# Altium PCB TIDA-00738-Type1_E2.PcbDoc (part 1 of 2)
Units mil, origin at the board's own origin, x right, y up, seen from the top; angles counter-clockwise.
Board outline 4723.41 x 3650 mil, 4 copper layers (Top Layer, GND, PWR, Bottom Layer), stack 79.834 mil thick; 251 components, 112 nets, 616 pads, 221 vias.
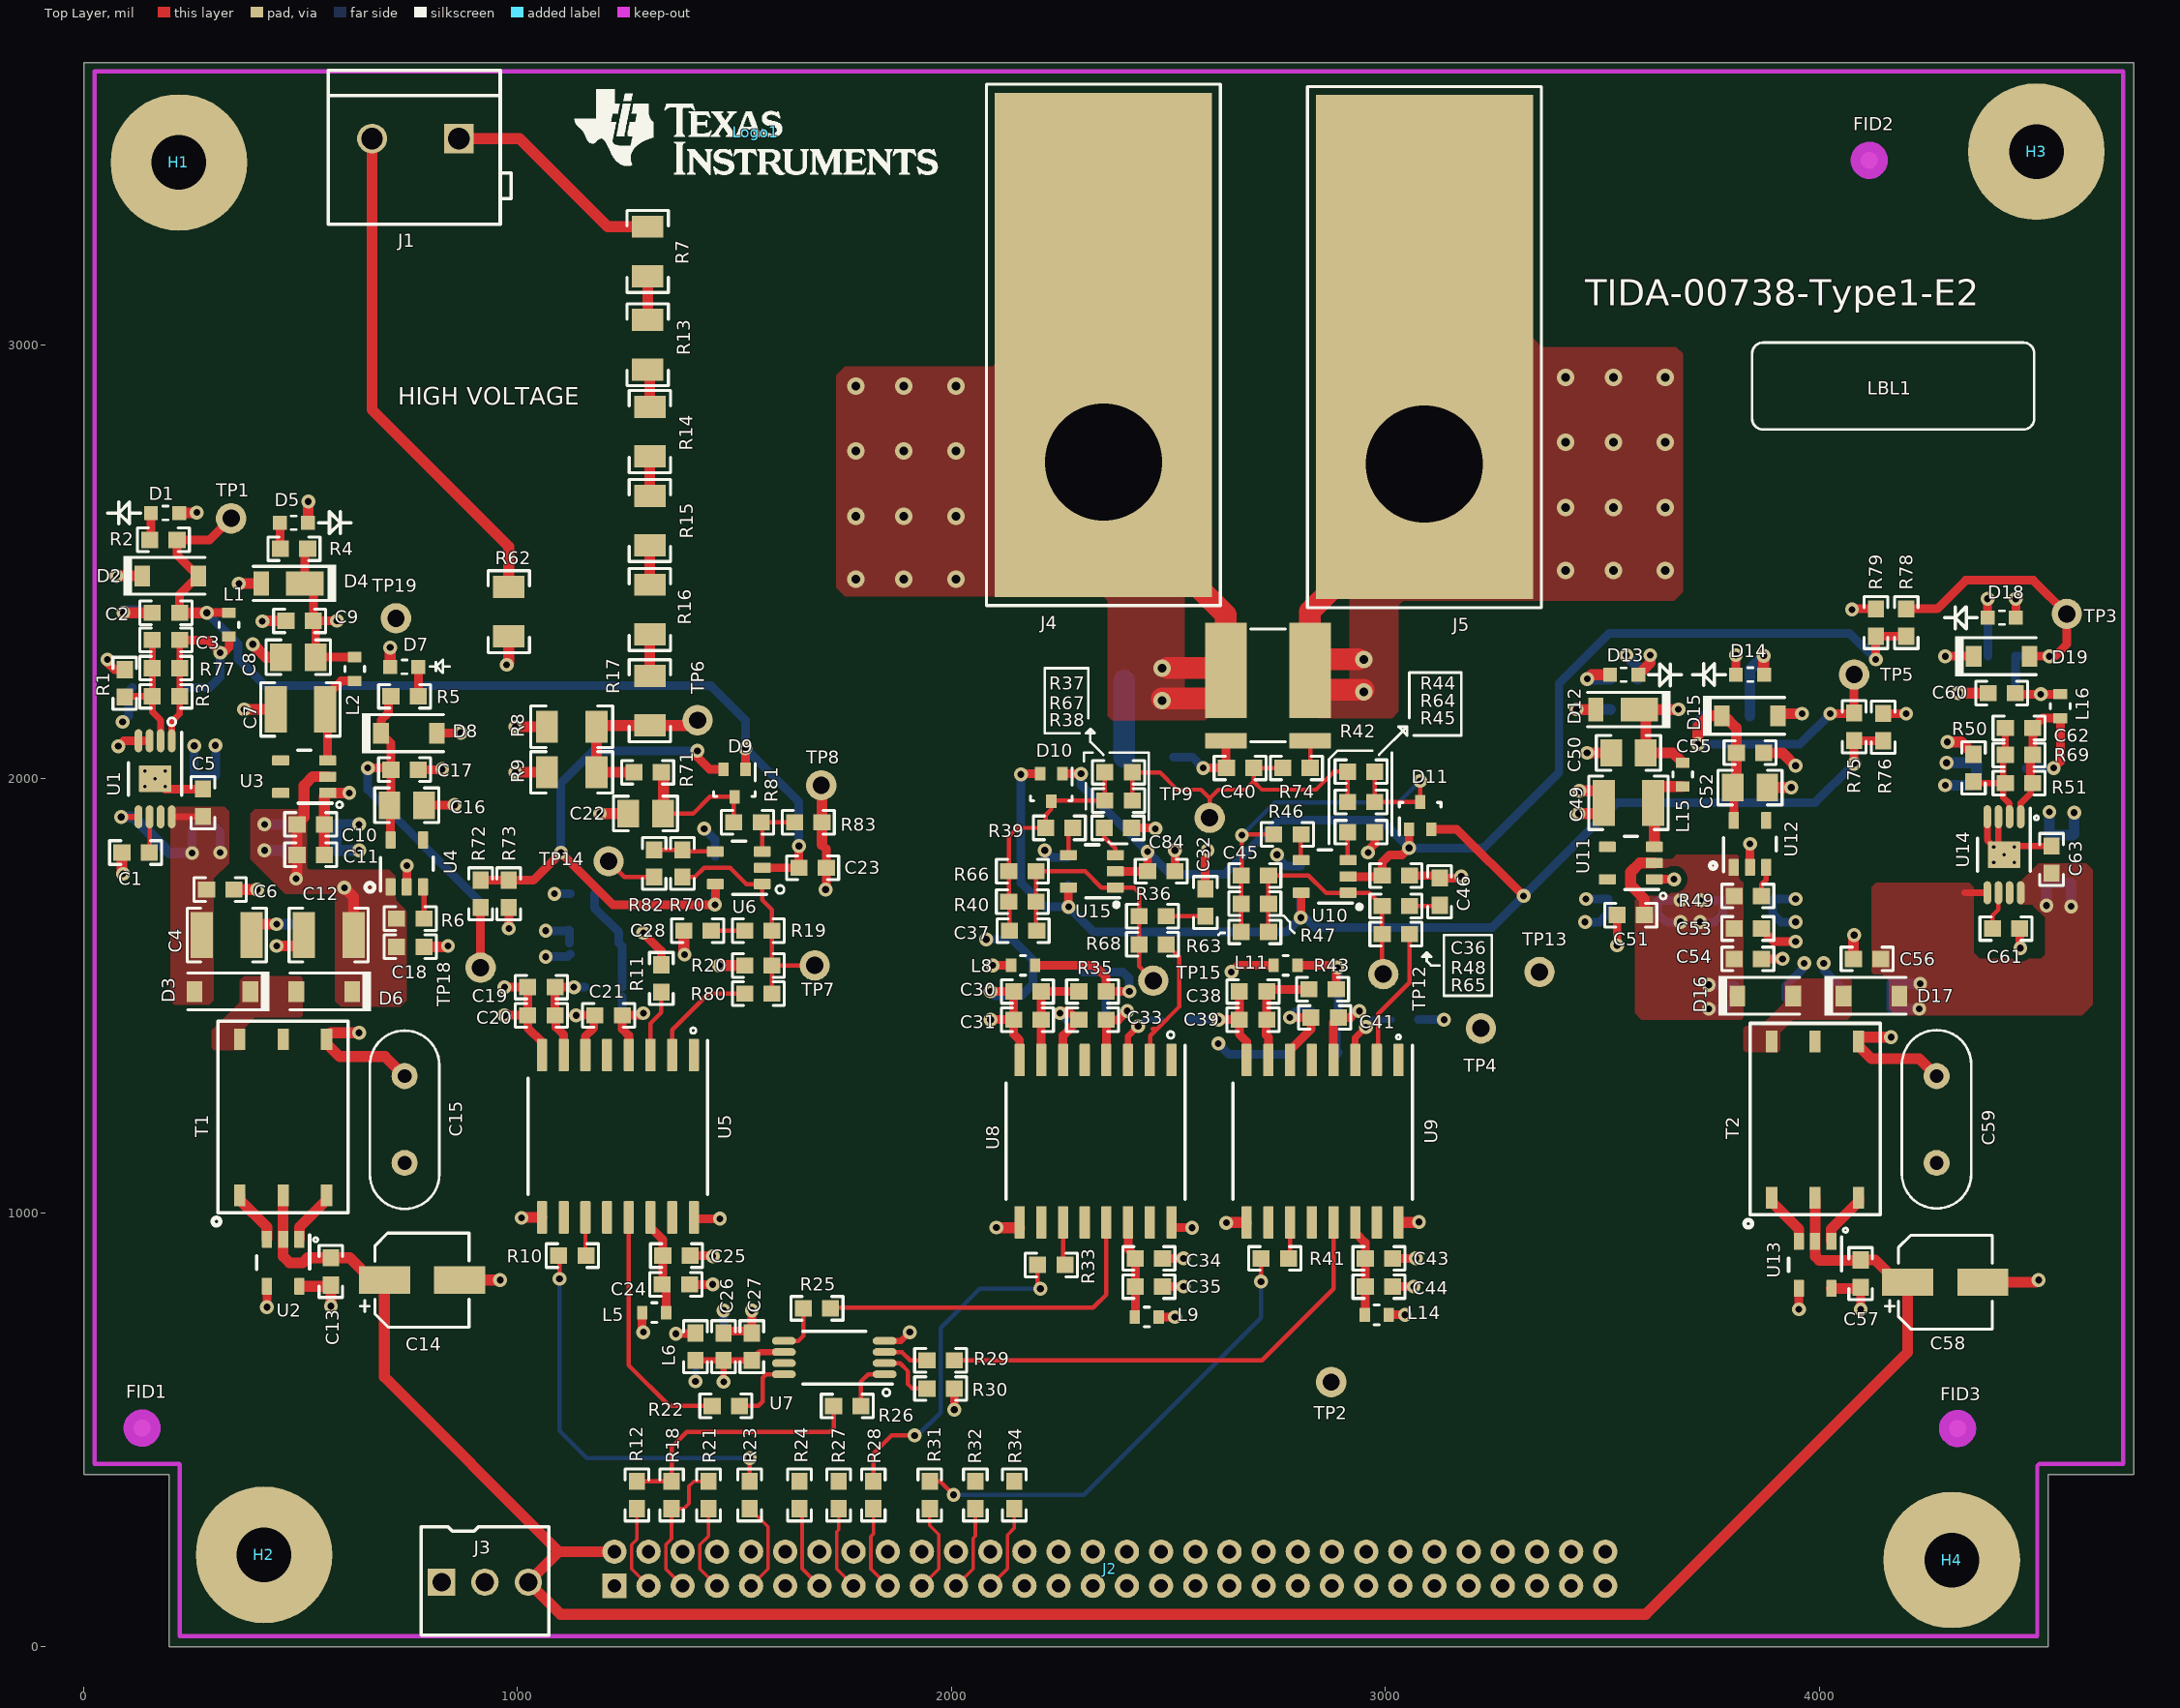
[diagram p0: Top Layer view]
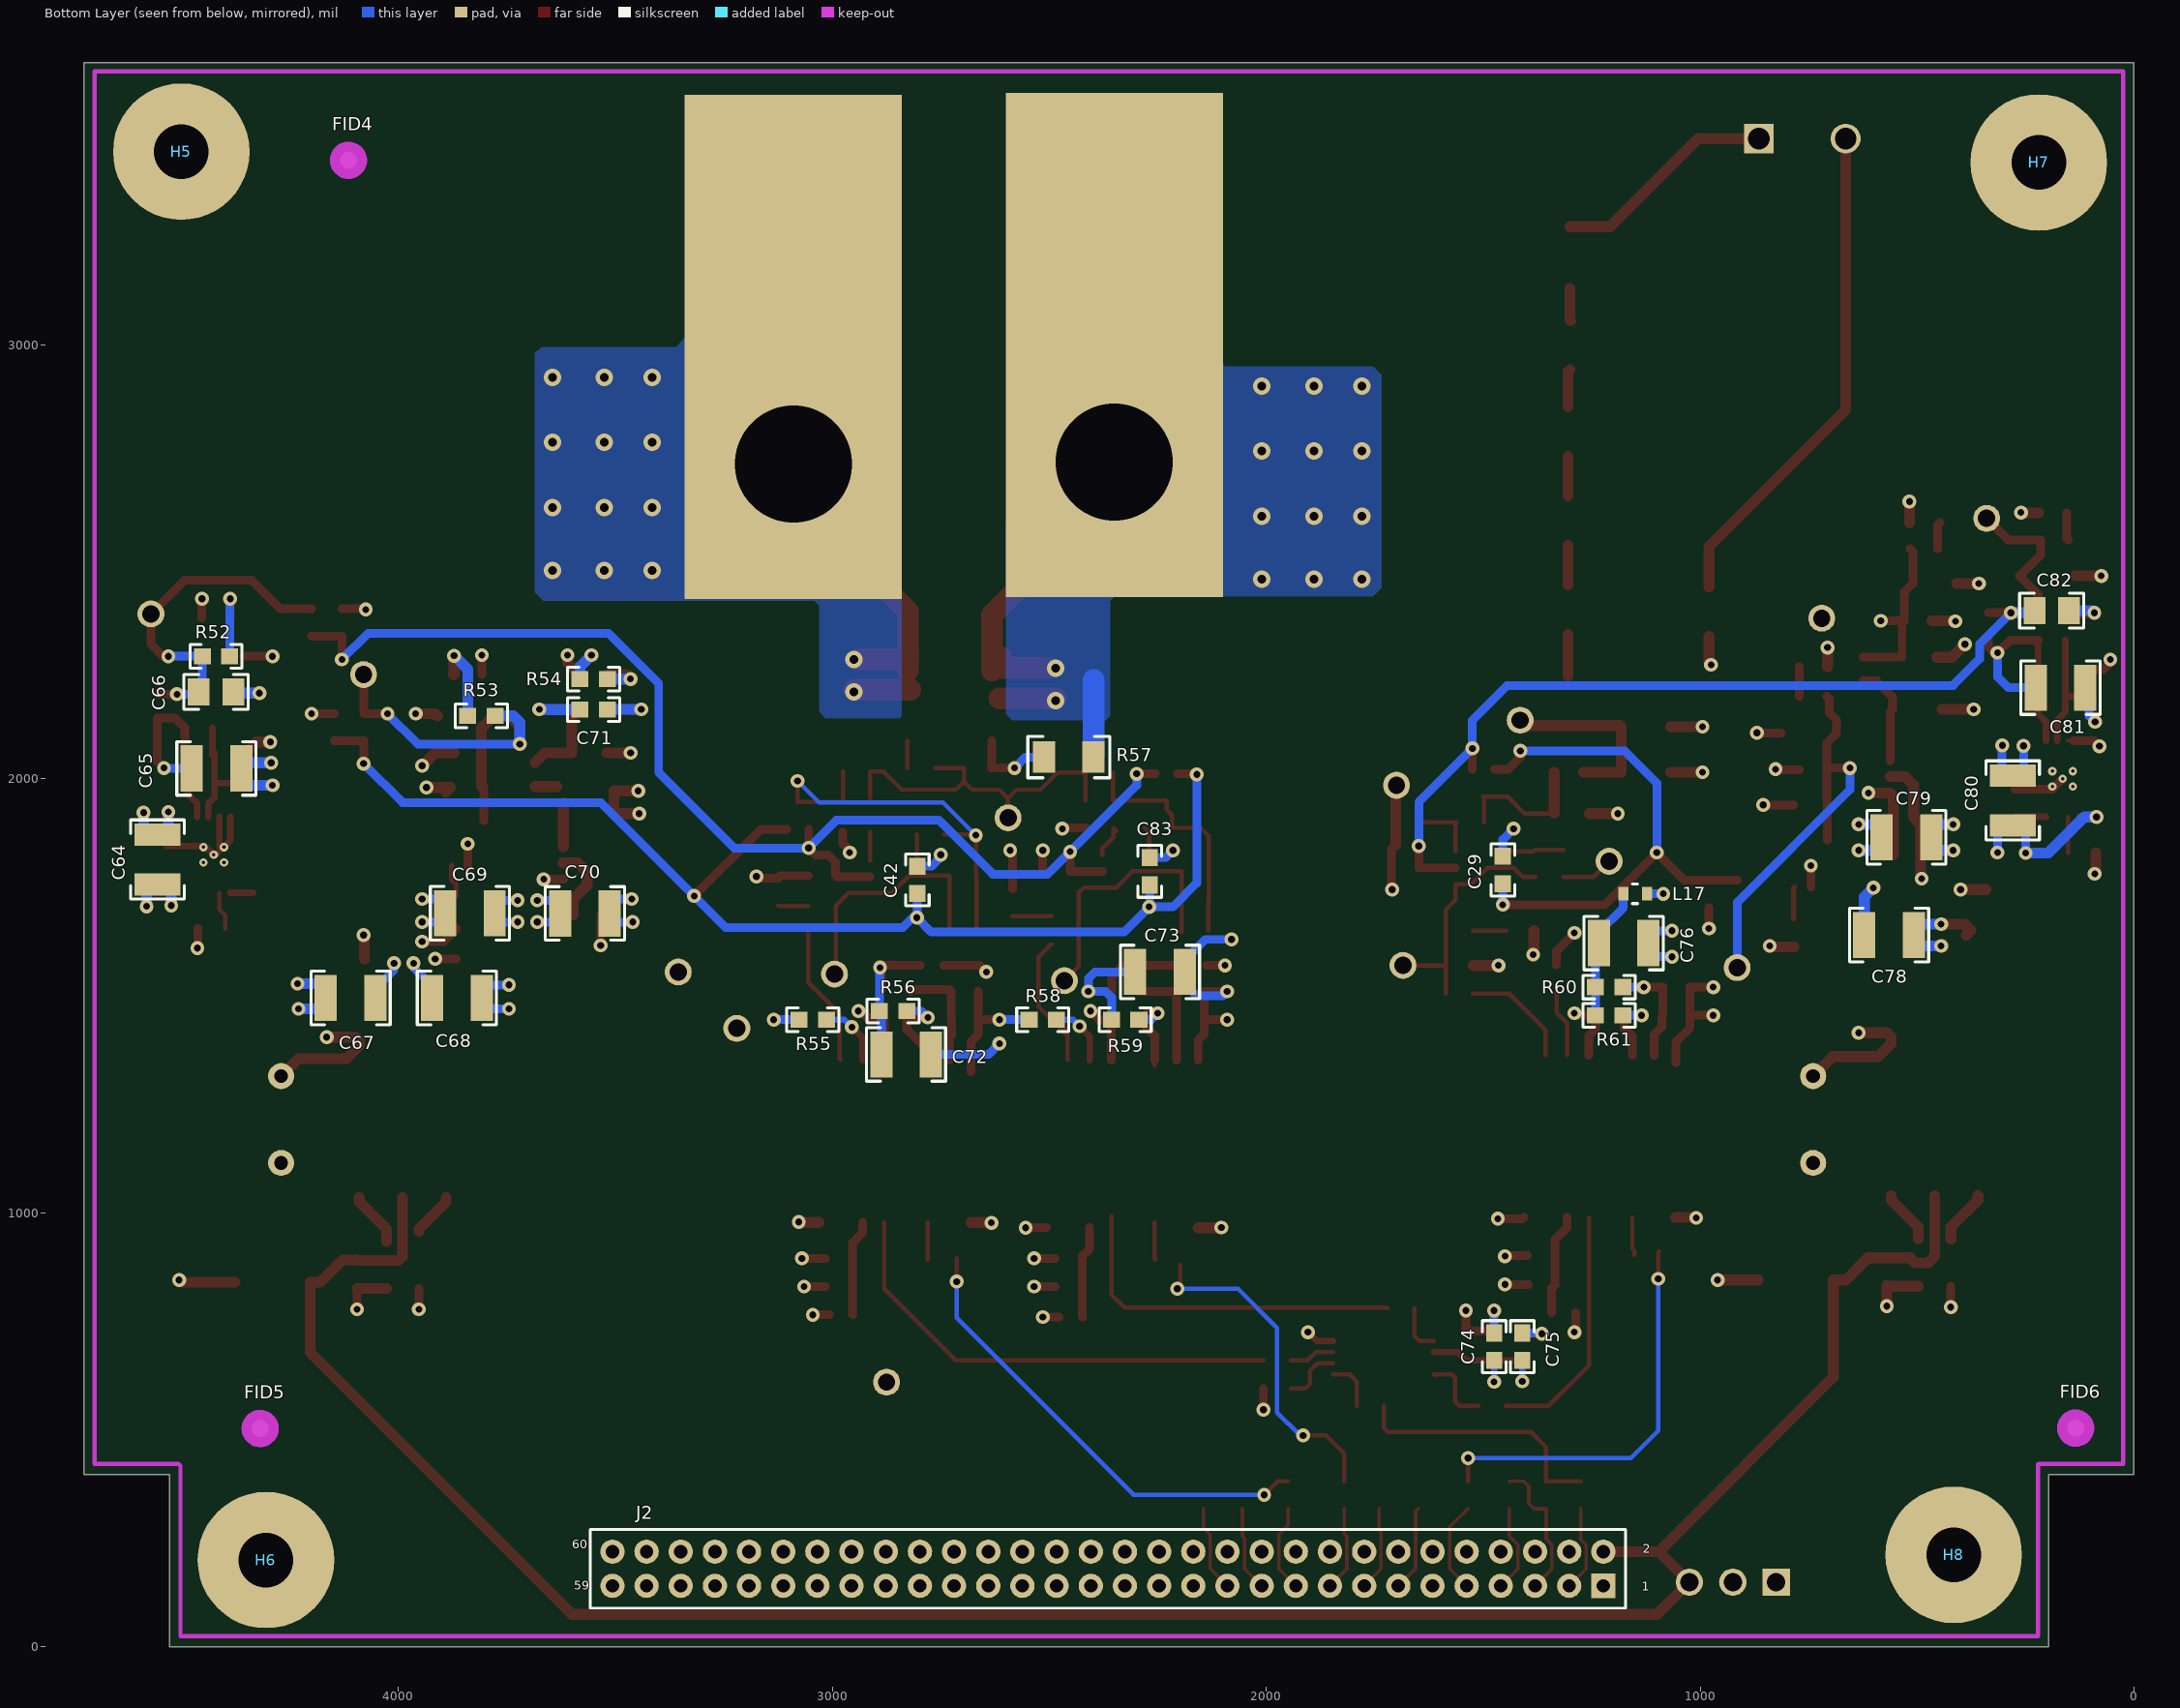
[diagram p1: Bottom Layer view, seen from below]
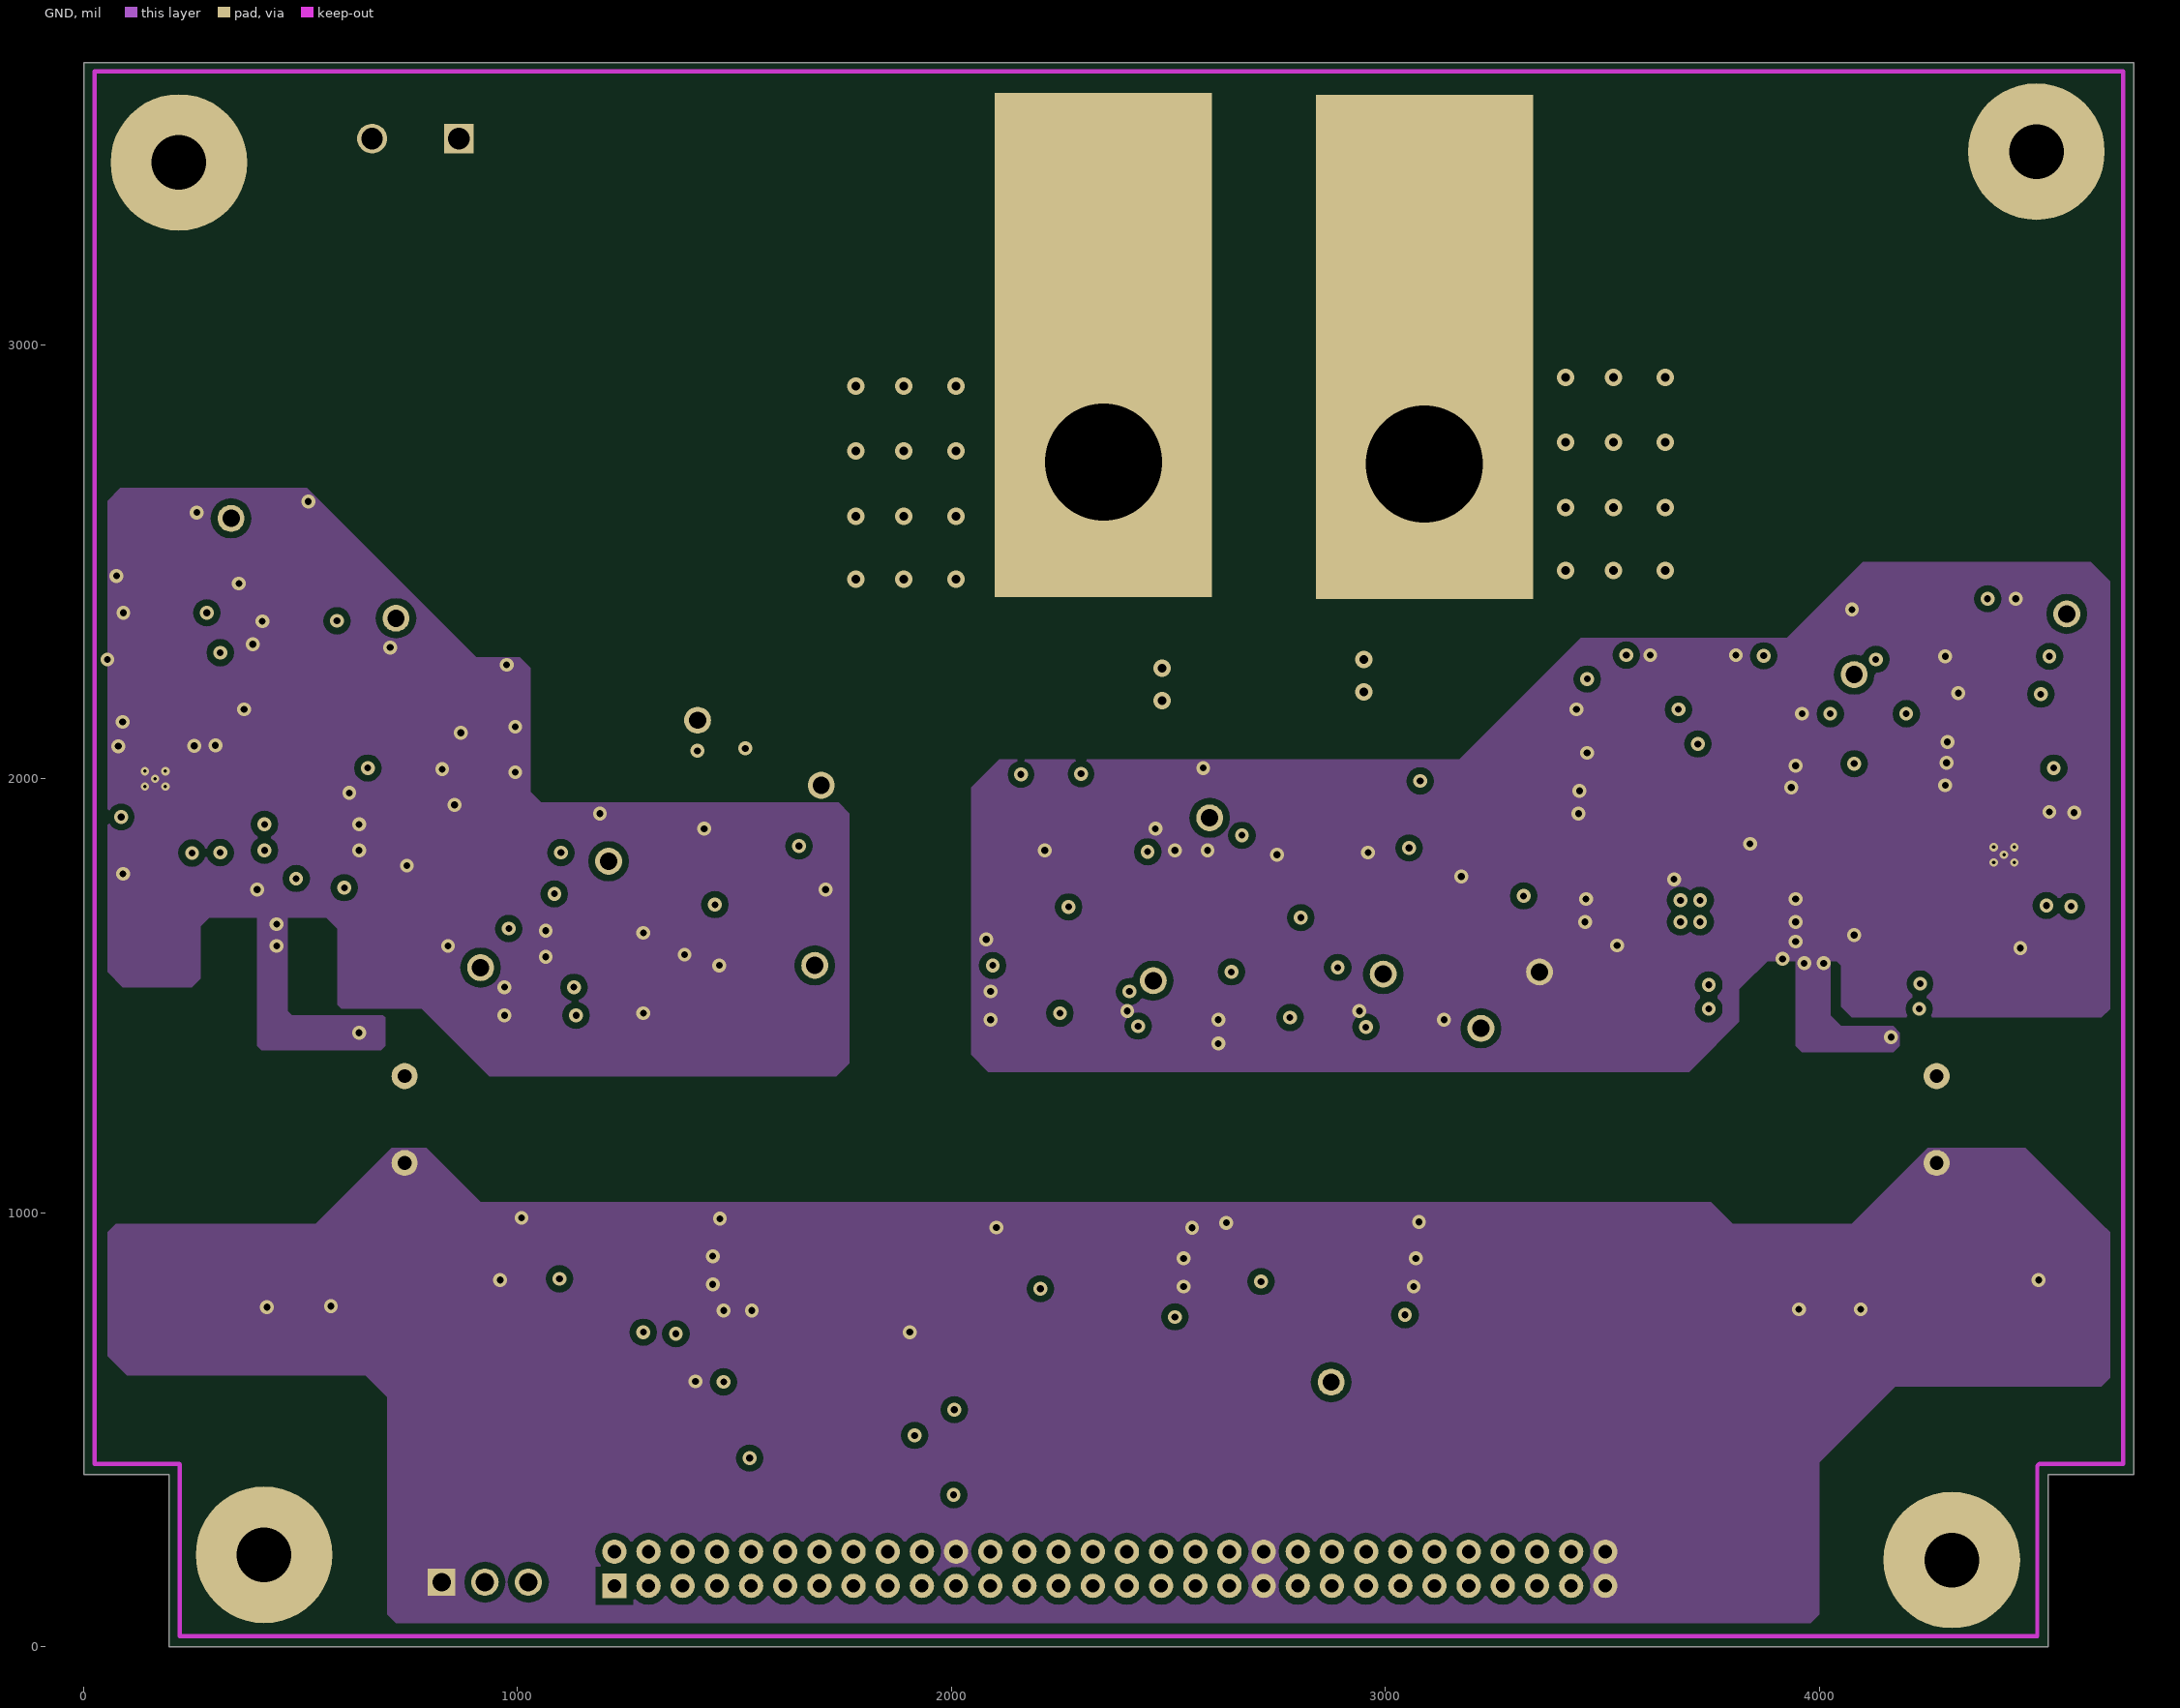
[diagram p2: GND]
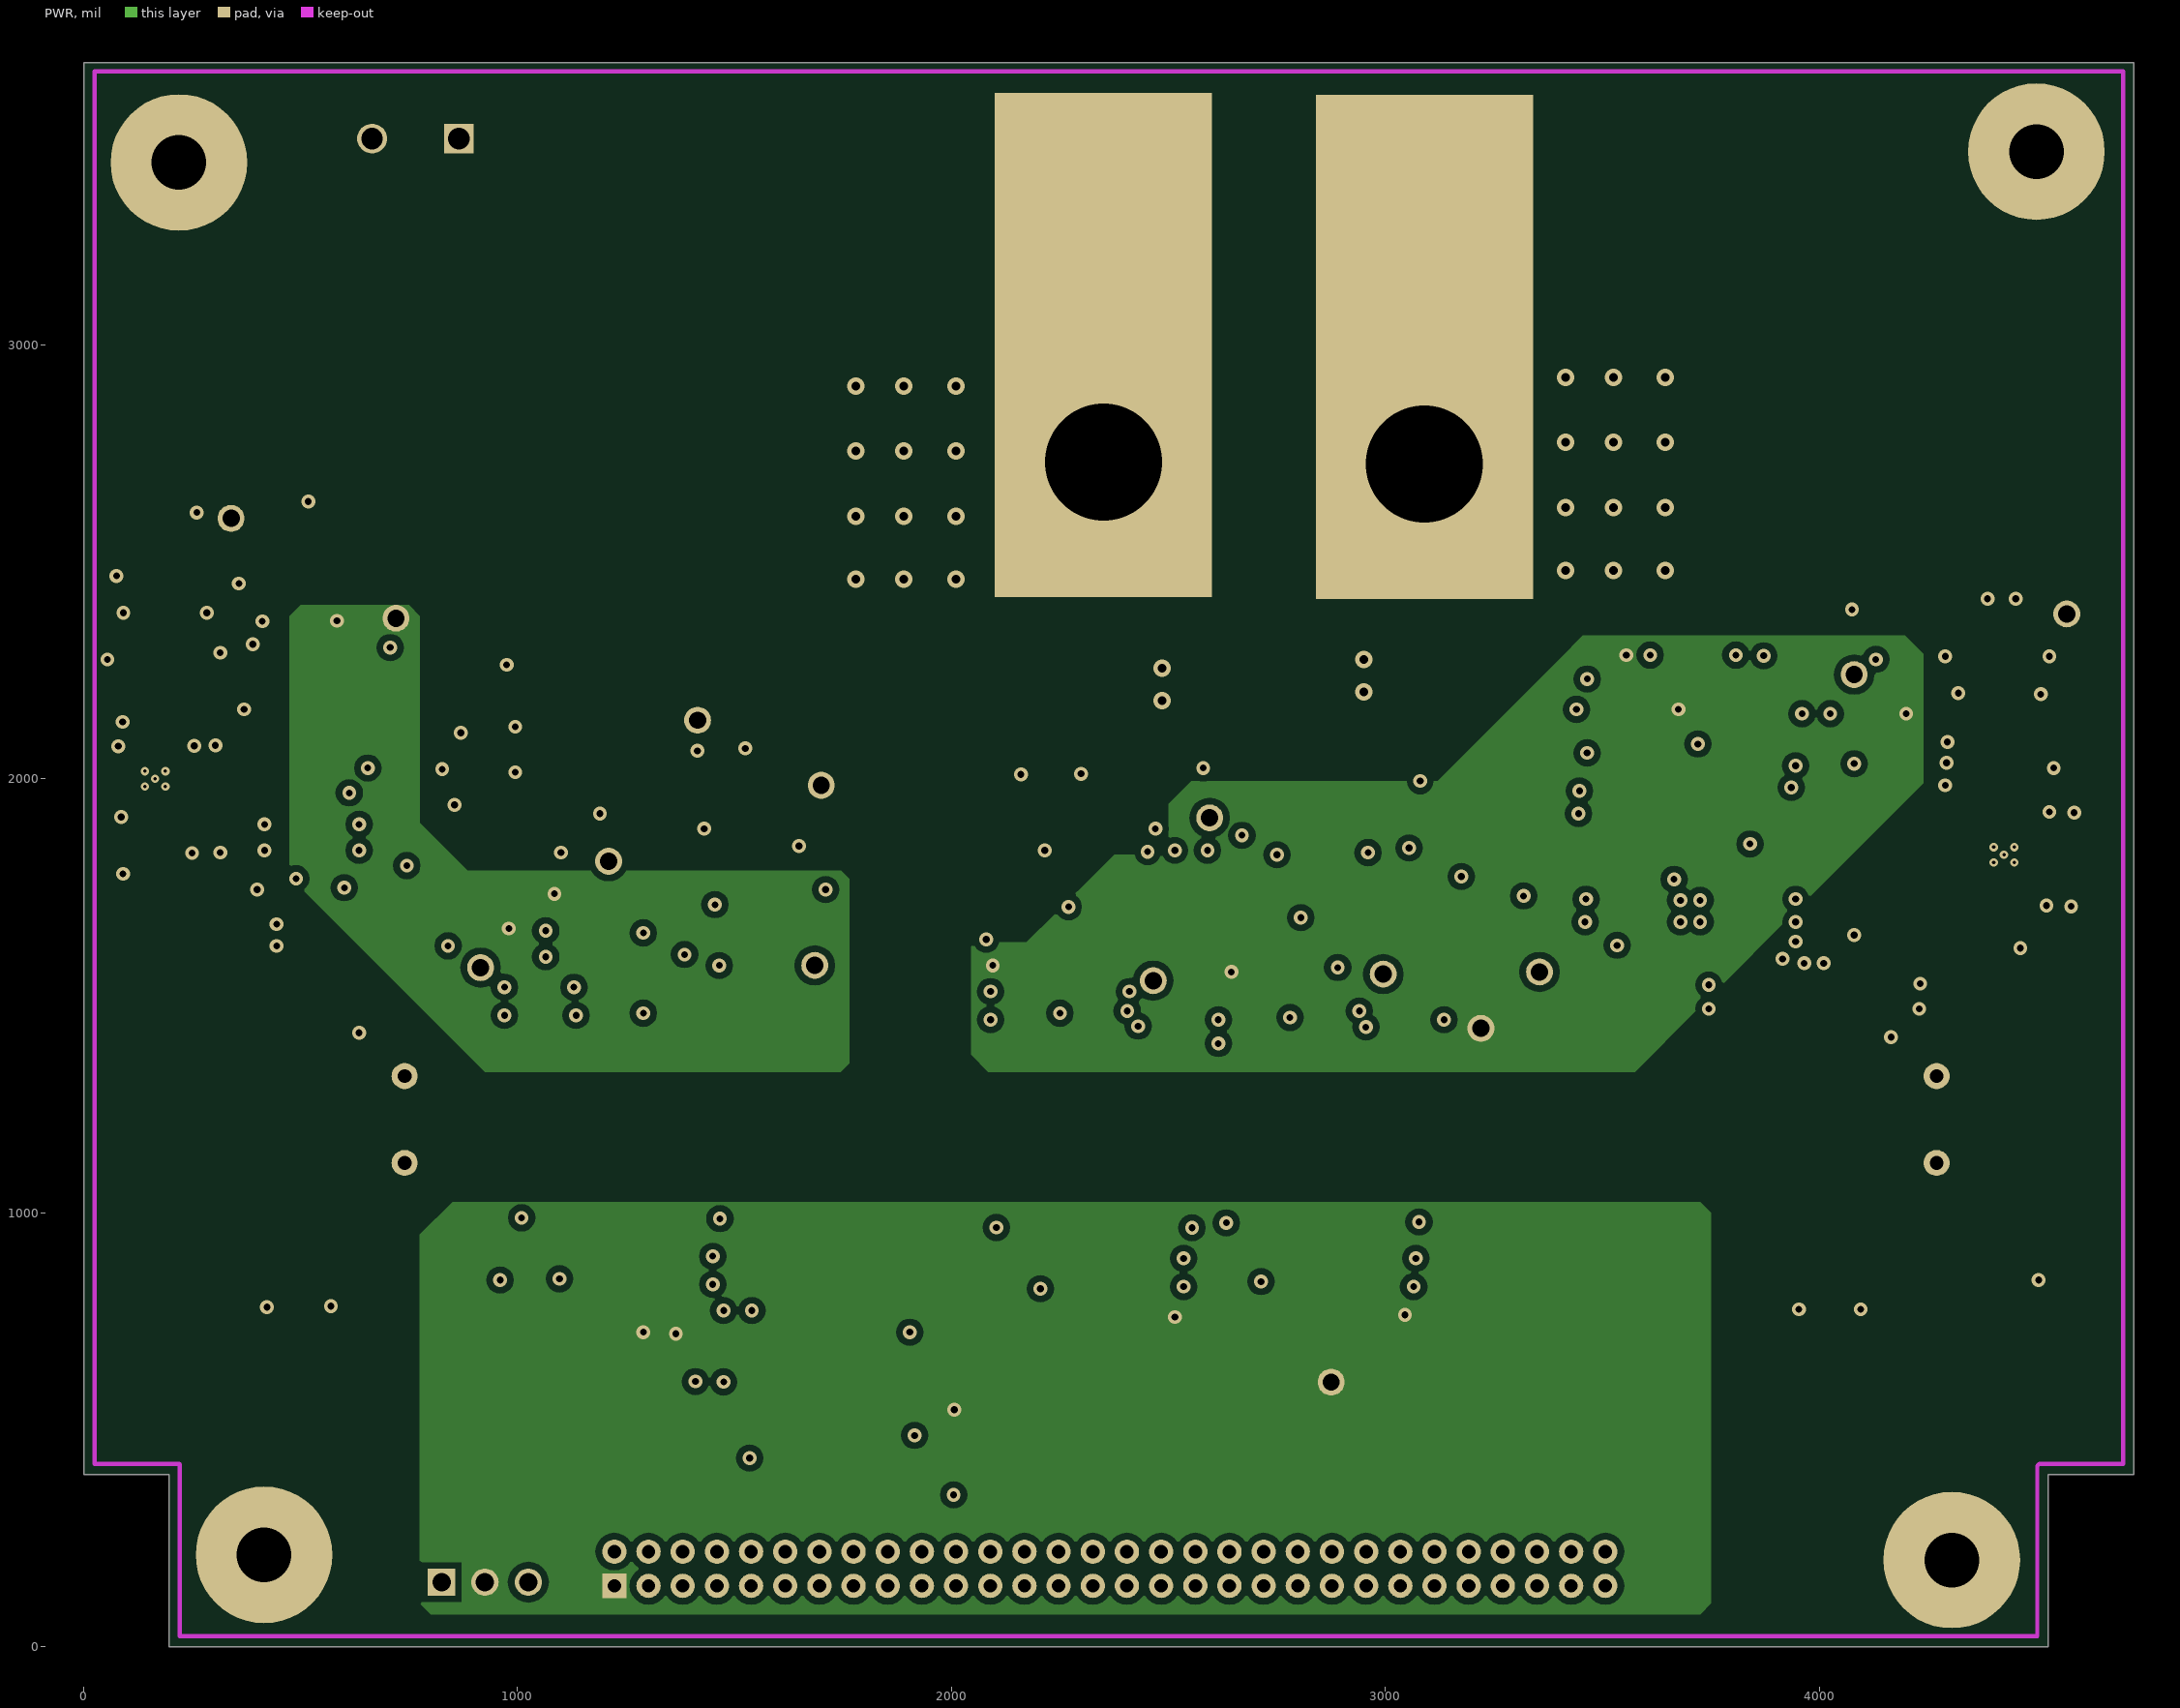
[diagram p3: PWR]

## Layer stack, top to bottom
Top Solder: solder mask 0.4, Solder Resist, Dk 3.5
Top Layer: signal copper 1.4
Dielectric1: core 59.2, FR-4, Dk 4.8
GND: signal copper 1.417
Dielectric 3: prepreg 5, Dk 4.2
PWR: signal copper 1.417
Dielectric 2: core 10, Dk 4.2
Bottom Layer: signal copper 1.4
Bottom Solder: solder mask 0.4, Solder Resist, Dk 3.5

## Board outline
1,396.7 1,3650 4724.41,3650 4724.41,396.7 4527,396.7 4527,0 196.85,0 196.85,396.7

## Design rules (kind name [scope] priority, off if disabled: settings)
AcuteAngle [All] p1: minimum=4.50000000000000E+0001 checktracksonly=FALSE
AssemblyTestPointUsage [All] p1: valid=2
Clearance Clearance_BoardEdge_MountingHoles [OnCopper and InComponentClass('Mounting Holes') vs IsKeepOut] p1: gap=12
Clearance Clearance_BoardEdge_Poly [OnCopper and InPoly vs IsKeepOut] p2: gap=25
Clearance Clearance_Poly [InPolygon] p3: gap=15
Clearance [All] p4: gap=7
ComponentClearance ComponentClearance_Logo [InComponentClass('Logo')] p1: gap=50 collisioncheckmode=3 verticalgap=10 showdistances=FALSE
ComponentClearance ComponentClearance_ScrewToNut [(HasFootprint('NY PMS 440 0025 PH')) vs (HasFootprint('Keystone_1902C'))] p2: gap=5 collisioncheckmode=3 verticalgap=10 showdistances=FALSE
ComponentClearance ComponentClearance_MountingHoles [InComponentClass('Mounting Holes')] p3: gap=250 collisioncheckmode=3 verticalgap=100000 showdistances=FALSE
ComponentClearance ComponentClearance_SmallPassives [HasFootprint('0201*') or HasFootprint('0402*') or HasFootprint('0508') or HasFootprint('0603*') or HasFootprint('0612') or HasFootprint('0805*') or HasFootprint('0815*') or HasFootprint('0830*') or HasFootprint('1206*') or HasFootprint('1210*') or HasFootprint('1808*') or HasFootprint('1812*') or HasFootprint('1825*') or HasFootprint('2010*') or HasFootprint('2220*') or HasFootprint('2225*') or HasFootprint('2512*') or HasFootprint('2728*') or HasFootprint('3518*') vs HasFootprint('0201*') or HasFootprint('0402*') or HasFootprint('0508') or HasFootprint('0603*') or HasFootprint('0612') or HasFootprint('0805*') or HasFootprint('0815*') or HasFootprint('0830*') or HasFootprint('1206*') or HasFootprint('1210*') or HasFootprint('1808*') or HasFootprint('1812*') or HasFootprint('1825*') or HasFootprint('2010*') or HasFootprint('2220*') or HasFootprint('2225*') or HasFootprint('2512*') or HasFootprint('2728*') or HasFootprint('3518*')] p4: gap=20 collisioncheckmode=3 verticalgap=10 showdistances=FALSE
ComponentClearance ComponentClearance_THtoSMT [IsThruComponent vs IsSMTComponent] p5: gap=30 collisioncheckmode=3 verticalgap=30 showdistances=FALSE
ComponentClearance ComponentClearance_THtoTH [IsThruComponent vs IsThruComponent] p6: gap=118.11 collisioncheckmode=3 verticalgap=30 showdistances=FALSE
ComponentClearance [All] p7: gap=25 collisioncheckmode=3 verticalgap=10 showdistances=FALSE
DiffPairsRouting [All] p1: maxlimit=100 minlimit=10 mostfreqgap=10 toplayer_minwidth=15 toplayer_maxwidth=15 toplayer_prefwidth=15 midlayer1_minwidth=15 midlayer1_maxwidth=15 midlayer1_prefwidth=15 midlayer2_minwidth=15 midlayer2_maxwidth=15 midlayer2_prefwidth=15 bottomlayer_minwidth=15 bottomlayer_maxwidth=15 bottomlayer_prefwidth=15 maxuncoupledlength=1000
FabricationTestPointUsage TestPointUsage [All] p1: valid=2 allowmultiple=FALSE
FabricationTestpoint Testpoint [All] p1: side=3 testpointundercomponent=TRUE minsize=40 maxsize=100 preferedsize=60 minholesize=0 maxholesize=40 preferedholesize=32 testpointgrid=1 allowsidetop=TRUE allowsidebottom=TRUE usegrid=TRUE gridtolerance=0.01
FanoutControl Fanout_LCC [IsLCC] p1: bgadir=Out bgaviamode=Centered fanoutstyle=Auto fanoutdirection=Alternating viagrid=1 // Fanout_LCC (Default Rule)
FanoutControl Fanout_BGA [IsBGA] p2: bgadir=Out bgaviamode=Centered fanoutstyle=Auto fanoutdirection=Alternating viagrid=1 // Fanout_BGA (Default Rule)
FanoutControl Fanout_Default [All] p4: bgadir=Out bgaviamode=Centered fanoutstyle=Auto fanoutdirection=Alternating viagrid=1 // Fanout_Default (Default Rule)
FanoutControl Fanout_Small [(CompPinCount < 5)] p5: bgadir=Out bgaviamode=Centered fanoutstyle=Auto fanoutdirection=OutThenIn viagrid=1 // Fanout_Small (Default Rule)
HoleSize [All] p1: absolutevalues=TRUE maxlimit=251 minlimit=7.87 maxpercent=80.000 minpercent=20.000
MinimumAnnularRing MinimumAnnularRing_ThermalPadVias [IsVia and InAnyComponent] p1: minimumring=5.91
MinimumAnnularRing [All] p2: minimumring=7
MinimumSolderMaskSliver MinimumSolderMaskSliver_Logo [InComponentClass('Logo') vs InComponentClass('Logo')] p1: minsoldermaskwidth=0.7
MinimumSolderMaskSliver [All] p2: minsoldermaskwidth=3.94
PlaneConnect [All] p1: planeconnectstyle=Direct reliefexpansion=10 reliefentries=4 reliefconductorwidth=10 reliefairgap=10
PolygonConnect [All] p1: connectstyle=Direct reliefconductorwidth=10 reliefentries=4 polygonreliefangle="90 Angle" airgapwidth=10
RoutingVias ThermalPadVias [IsVia and InAnyComponent] p1: holewidth=7.87 width=19.68 viastyle="Through Hole" minholewidth=7.87 minwidth=19.68 maxholewidth=12.99 maxwidth=23.62
RoutingVias [All] p2: holewidth=16 width=32 viastyle="Through Hole" minholewidth=7.87 minwidth=26 maxholewidth=40 maxwidth=65
SMDToCorner [All] p1: distance=30000
SilkToSilkClearance [All] p1: silktosilkclearance=3
SilkToSolderMaskClearance SilkscreenOverComponentPads [IsPad] p1: minsilkscreentomaskgap=5 clearancetoexposedcopper=TRUE
SolderMaskExpansion [All] p1: expansion=1.97
UnpouredPolygon [All] p1: allowunpoured=FALSE
Width [All] p1: maxlimit=100 minlimit=6 preferedwidth=10 checkconnectedcopper=TRUE
15 further rules are at their usual default settings.

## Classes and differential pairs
component class "Clock Generator": C26 C27 C74 C75 J2 J3 L6 R12 R18 R21 R22 R23 R24 R25 R26 R27 R28 R29 R30 R31 R32 R34 U7
component class "Power Supply Voltage Measurement": C1 C2 C3 C4 C5 C6 C7 C8 C9 C10 C11 C12 C13 C14 C15 C16 C17 C18 C78 C79 C80 C81 C82 D1 D2 D3 D4 D5 D6 D7 D8 D22 FB11 FB12 FB13 FB14 L1 L2 R1 R2 R3 R4 R5 R6 R77 T1 TP1 TP18 TP19 U1 U2 U3 U4
component class "Power Supply Current Measurment": C49 C50 C51 C52 C53 C54 C55 C56 C57 C58 C59 C60 C61 C62 C63 C64 C65 C66 C67 C68 C69 C70 C71 D12 D13 D14 D15 D16 D17 D18 D19 FB7 FB8 FB9 L15 L16 R49 R50 R51 R52 R53 R54 R69 T2 TP3 TP4 TP5 U11 U12 U13 U14
component class "Current Measurement": C30 C31 C32 C33 C34 C35 C36 C37 C38 C39 C40 C41 C42 C43 C44 C45 C46 C72 C73 C83 C84 D10 D11 FB1 FB2 FB3 FB4 FB5 j4 J5 L8 L9 L11 L14 R33 R35 R36 R37 R38 R39 R40 R41 R42 R43 R44 R45 R46 R47 R48 R55 R56 R57 R58 R59 R63 R64 R65 R66 R67 R68 R74 R75 R76 R78 R79 TP9 TP12 TP13 TP15 U8 U9 U10 U15
component class "Mounting Holes": H1 H2 H3 H4
component class Logo: Logo1
component class Hardware_ANSI-B: FID1 FID2 FID3 FID4 FID5 FID6 H1 H2 H3 H4 H5 H6 H7 H8 LBL1 Logo1 ZZ1 ZZ2 ZZ3 ZZ4
component class FiducialMark: FID1 FID2 FID3 FID4 FID5 FID6
component class AssemblyNote: ZZ1 ZZ2 ZZ3 ZZ4
component class Label: LBL1
component class "Voltage Measurment": C19 C20 C21 C22 C23 C24 C25 C28 C29 C76 D9 J1 L5 L17 R7 R8 R9 R10 R11 R13 R14 R15 R16 R17 R19 R20 R60 R61 R62 R70 R71 R72 R73 R80 R81 R82 R83 TP2 TP6 TP7 TP8 TP14 U5 U6

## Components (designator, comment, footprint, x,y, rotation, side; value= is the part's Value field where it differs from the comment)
C1 "" 0603 120,1830 r0 top (schematic designator C86)
C2 "" 0603 190,2382.5 r180 top (schematic designator C67)
C3 "" 0603 190,2320 r0 top (schematic designator C62)
C4 "" 1210 330,1640 r180 top (schematic designator C77)
C5 "" 0603 275,1945 r90 top (schematic designator C61)
C6 "" 0603 315,1745 r180 top (schematic designator C78)
C7 "" 1210 500,2160 r0 top (schematic designator C54)
C8 "" 0805_HV 495,2280 r0 top (schematic designator C49)
C9 "" 0603 498,2364 r180 top (schematic designator C51)
C10 "" 0603 523.47,1894.8 r0 top (schematic designator C55)
C11 "" 0603 523.47,1824.8 r0 top (schematic designator C70)
C12 "" 1210 565,1640 r180 top (schematic designator C69)
C13 "" 0603 570,865 r90 top (schematic designator C68)
C14 "UUD1E220MCL1GS" SM_RADIAL_5MM 780,845 r0 top (schematic designator C60)
C15 "" CAP_200mil 740,1215 r90 top (schematic designator C66)
C16 "" 0805_HV 745,1939 r180 top (schematic designator C89)
C17 "" 0603 740,2021 r0 top (schematic designator C90)
C18 "" 0603 753,1613 r0 top (schematic designator C88)
C19 "" 0603 1055,1520 r180 top (schematic designator C64)
C20 "" 0603 1055,1455 r180 top (schematic designator C7)
C21 "" 0603 1210,1455 r0 top (schematic designator C65)
C22 "GRM2195C1H103JA01D" 0805_HV 1295,1920 r0 top (schematic designator C92)
C23 "" 0603 1680,1795 r180 top (schematic designator C1)
C24 "GRM188R71A225KE15D" 0603 1365,835 r180 top (schematic designator C4)
C25 "" 0603 1366.5,901.5 r180 top (schematic designator C57)
C26 "06033C104JAT2A" 0603 1475,691.46 r90 top (schematic designator C21)
C27 "06033C104JAT2A" 0603 1540,691.46 r90 top (schematic designator C22)
C28 "GRM188R72A104KA35D" 0603 1415,1650 r180 top (schematic designator C3)
C29 "" 0603 1455,1790 r270 bottom (schematic designator C11)
C30 "" 0603 2175,1510 r180 top (schematic designator C18)
C31 "" 0603 2175,1445 r180 top (schematic designator C34)
C32 "GRM188R72A104KA35D" 0603 2585,1715 r90 top (schematic designator C56)
C33 "" 0603 2325,1445 r0 top (schematic designator C19)
C34 "" 0603 2455,895 r180 top (schematic designator C12)
C35 "GRM188R71A225KE15D" 0603 2455,830 r180 top (schematic designator C33)
C36 "" 0603 3023.97,1777.13 r180 top (schematic designator C13)
C37 "GRM1885C1H102FA01J" 0603 2165,1650 r180 top (schematic designator C16)
C38 "" 0603 2695,1510 r180 top (schematic designator C10)
C39 "" 0603 2695,1445 r180 top (schematic designator C26)
C40 "GRM1885C1H102FA01J" 0603 2665,2025 r180 top (schematic designator C5)
C41 "" 0603 2860,1450 r0 top (schematic designator C15)
C42 "" 0603 2803.97,1767.13 r270 bottom (schematic designator C8)
C43 "" 0603 2985,895 r180 top (schematic designator C2)
C44 "GRM188R71A225KE15D" 0603 2985,830 r180 top (schematic designator C20)
C45 "GRM1885C1H102FA01J" 0603 2698.97,1777.13 r180 top (schematic designator C6)
C46 "GRM188R72A104KA35D" 0603 3124.97,1739.93 r90 top (schematic designator C14)
C49 "" 1210 3560,1944.68 r0 top (schematic designator C54)
C50 "" 0805_HV 3560,2059.68 r0 top (schematic designator C49)
C51 "" 0603 3565.31,1685.98 r180 top (schematic designator C55)
C52 "" 0805_HV 3840,1980 r180 top (schematic designator C50)
C53 "" 0603 3835,1655 r0 top (schematic designator C48)
C54 "" 0603 3835,1585 r0 top (schematic designator C29)
C55 "" 0603 3840,2060 r0 top (schematic designator C52)
C56 "" 0603 4110,1585 r0 top (schematic designator C32)
C57 "" 0603 4095,860 r90 top (schematic designator C27)
C58 "UUD1E220MCL1GS" SM_RADIAL_5MM 4290,840 r0 top (schematic designator C30)
C59 "" CAP_200mil 4270,1215 r90 top (schematic designator C25)
C60 "" 0603 4420.02,2197.27 r180 top (schematic designator C43)
C61 "" 0603 4430,1655 r180 top (schematic designator C46)
C62 "" 0603 4460.02,2117.27 r0 top (schematic designator C42)
C63 "" 0603 4535,1814.02 r90 top (schematic designator C41)
C64 "" 1210 4555,1814.02 r270 bottom (schematic designator C39)
C65 "" 1210 4419.07,2024.02 r0 bottom (schematic designator C44)
C66 "" 0805_HV 4420,2200 r0 bottom (schematic designator C40)
C67 "" 1210 4110,1495 r0 bottom (schematic designator C31)
C68 "" 1210 3865,1495 r0 bottom (schematic designator C28)
C69 "" 1210 3835,1690 r180 bottom (schematic designator C47)
C70 "" 1210 3570,1689.68 r0 bottom (schematic designator C53)
C71 "" 0603 3550,2159.68 r180 bottom (schematic designator C51)
C72 "" 1210 2830,1365 r0 bottom (schematic designator C9)
C73 "" 1210 2245,1555 r0 bottom (schematic designator C17)
C74 "06033C104JAT2A" 0603 1475,691.46 r90 bottom (schematic designator C23)
C75 "GRM188R71A105KA61D" 0603 1410,691.46 r270 bottom (schematic designator C24)
C76 "" 1210 1176.5,1621.5 r0 bottom (schematic designator C63)
C78 "" 1210 565,1640 r0 bottom (schematic designator C87)
C79 "" 1210 525,1865 r180 bottom (schematic designator C53)
C80 "" 1210 280,1950 r270 bottom (schematic designator C58)
C81 "" 1210 170,2210 r0 bottom (schematic designator C85)
C82 "" 0805_HV 190,2387.5 r0 bottom (schematic designator C59)
C83 "" 0603 2268.53,1786.93 r270 bottom
C84 "" 0603 2483.53,1786.93 r180 top
D1 "" LED0603AA 188,2612.5 r0 top (schematic designator D17)
D2 "MMSZ5228B-7-F" SOD-123 200,2467.5 r0 top (schematic designator D6)
D3 "MBR0520L" SOD-123 320,1510 r180 top (schematic designator D22)
D4 "" powerDI123 460,2450 r180 top (schematic designator D13)
D5 "" LED0603AA 485,2590 r180 top (schematic designator D15)
D6 "MBR0520L" SOD-123 555,1510 r180 top (schematic designator D19)
D7 "" LED0603AA 739,2258 r0 top (schematic designator D25)
D8 "MMSZ5228B-7-F" SOD-123 750,2105 r0 top (schematic designator D18)
D9 "BAT54SWT1G" SOT-323 1500,1990 r270 top (schematic designator D1)
D10 "BAT54SWT1G" SOT-323 2230,1980 r270 top (schematic designator D4)
D11 "BAT54SWT1G" SOT-323 3080,1915 r90 top (schematic designator D2)
D12 "" powerDI123 3535,2159.68 r180 top (schematic designator D13)
D13 "" LED0603AA 3550,2239.68 r180 top (schematic designator D15)
D14 "" LED0603AA 3840,2240 r0 top (schematic designator D16)
D15 "MMSZ5228B-7-F" SOD-123 3840,2145 r0 top (schematic designator D14)
D16 "MBR0520L" SOD-123 3875,1500 r0 top (schematic designator D7)
D17 "MBR0520L" SOD-123 4120,1500 r0 top (schematic designator D8)
D18 "" LED0603AA 4420.02,2371.28 r0 top (schematic designator D12)
D19 "MMSZ5228B-7-F" SOD-123 4420.02,2282.27 r0 top (schematic designator D10)
FID1 "Fiducial" Fiducial10-20 135,504 r90 top (schematic designator FID3)
FID2 "Fiducial" Fiducial10-20 4115,3425 r90 top (schematic designator FID3)
FID3 "Fiducial" Fiducial10-20 4318.31,503 r90 top
FID4 "Fiducial" Fiducial10-20 4115,3425 r90 bottom (schematic designator FID3)
FID5 "Fiducial" Fiducial10-20 4318.31,503 r90 bottom (schematic designator FID3)
FID6 "Fiducial" Fiducial10-20 135,504 r90 bottom (schematic designator FID3)
H1 "NY PMS 440 0025 PH" "NY PMS 440 0025 PH" 220,3420 r0 top
H2 "NY PMS 440 0025 PH" "NY PMS 440 0025 PH" 416.02,212.01 r0 top locked (schematic designator H1)
H3 "NY PMS 440 0025 PH" "NY PMS 440 0025 PH" 4500,3445 r0 top
H4 "NY PMS 440 0025 PH" "NY PMS 440 0025 PH" 4305,200 r0 top locked (schematic designator H2)
H5 "1902C" Keystone_1902C 4500,3445 r180 bottom locked (schematic designator H8)
H6 "1902C" Keystone_1902C 4305,200 r180 bottom locked
H7 "1902C" Keystone_1902C 220,3420 r180 bottom locked
H8 "1902C" Keystone_1902C 416.02,212.01 r180 bottom locked (schematic designator H5)
J1 "ED120/2DS" CONN_ED120-2DS 765,3475 r90 top (schematic designator J9)
J2 "NRPN302PAEN-RC" CONN_NRPN302PAEN-RC 2365,180 r0 top
J3 "22-11-2032" Molex_22-11-2032 925,149 r0 top
J4 "LAMA2-14-QY" PANDUIT_LAMA2-14-QY 2350,2730 r270 top (schematic designator TP10)
J5 "LAMA2-14-QY" PANDUIT_LAMA2-14-QY 3090,2725 r270 top (schematic designator TP11)
L1 "MMZ1608B102CTA00" MMZ1608_095 335,2355 r90 top
L2 "MMZ1608B102CTA00" MMZ1608_095 625,2253 r90 top (schematic designator L9)
L5 "MMZ1608B102CTA00" MMZ1608_095 1315,770 r180 top (schematic designator L10)
L6 "BLM18KG601SN1D" 0603 1410,691.46 r270 top (schematic designator L14)
L8 "MMZ1608B102CTA00" MMZ1608_095 2165,1570 r180 top (schematic designator L18)
L9 "MMZ1608B102CTA00" MMZ1608_095 2450,760 r0 top (schematic designator L17)
L11 "MMZ1608B102CTA00" MMZ1608_095 2770,1570 r180 top (schematic designator L16)
L14 "MMZ1608B102CTA00" MMZ1608_095 2980,765 r0 top (schematic designator L15)
L15 "MMZ1608B102CTA00" MMZ1608_095 3685,2009.68 r90 top (schematic designator L9)
L16 "MMZ1608B102CTA00" MMZ1608_095 4555.02,2167.27 r90 top (schematic designator L8)
L17 "MMZ1608B102CTA00" MMZ1608_095 1150,1735 r180 bottom (schematic designator L12)
LBL1 "Size: 0.65\" x 0.20 \"" Label_650x200 4170,2905 r0 top
Logo1 "Texas Instruments" TI_Stacked_Overlay_Small 1550,3490 r0 top
R1 "CRCW060310K2FKEA" 0603 95,2220 r270 top (schematic designator R56)
R2 "RC0603FR-071K2L" 0603 184,2550.5 r0 top (schematic designator R42)
R3 "CRCW060311K3FKEA" 0603 190,2190 r0 top (schematic designator R45)
R4 "RC0603FR-071K2L" 0603 485,2530 r0 top (schematic designator R29)
R5 "RC0603FR-071K2L" 0603 740,2190 r180 top (schematic designator R59)
R6 "" 0603 753,1678 r180 top (schematic designator R58)
R7 "RC1206JR-070RL" 1206 1300,3215 r270 top
R8 "RC1206FR-071K02L" 1206 1125,2120 r0 top (schematic designator R39)
R9 "RC1206FR-072K4L" 1206 1125,2015 r0 top (schematic designator R40)
R10 "" 0603 1126.5,901.5 r180 top (schematic designator R44)
R11 "" 0603 1331.5,1540 r270 top (schematic designator R41)
R12 "CRCW06030000Z0EA" 0603 1275,350 r270 top (schematic designator R21)
R13 "ERJ-8ENF3323V" 1206 1300,3000 r270 top (schematic designator R8)
R14 "ERJ-8ENF3323V" 1206 1305,2800 r270 top (schematic designator R32)
R15 "ERJ-8ENF3323V" 1206 1305,2595 r270 top (schematic designator R33)
R16 "ERJ-8ENF3323V" 1206 1305,2390 r270 top (schematic designator R34)
R17 "ERJ-8ENF3323V" 1206 1305,2180 r270 top (schematic designator R35)
R18 "CRCW06030000Z0EA" 0603 1355,350 r270 top (schematic designator R57)
R19 "RC0603FR-0710RL" 0603 1555,1650 r0 top (schematic designator R2)
R20 "CRCW0603100KJNEA" 0603 1555,1570 r0 top (schematic designator R3)
R21 "CRCW06030000Z0EA" 0603 1440,350 r270 top (schematic designator R31)
R22 "CRCW0603100RFKEA" 0603 1480,555 r0 top (schematic designator R69)
R23 "CRCW06030000Z0EA" 0603 1535,350 r270 top (schematic designator R36)
R24 "CRCW06030000Z0EA" 0603 1650,350 r270 top (schematic designator R38)
R25 "CRCW0603100RFKEA" 0603 1690,780 r180 top (schematic designator R71)
R26 "CRCW0603100RFKEA" 0603 1760,555 r180 top (schematic designator R70)
R27 "CRCW06030000Z0EA" 0603 1740,350 r270 top (schematic designator R50)
R28 "CRCW06030000Z0EA" 0603 1820,350 r270 top (schematic designator R51)
R29 "CRCW0603100RFKEA" 0603 1975,660 r180 top (schematic designator R61)
R30 "CRCW06031K00JNEA" 0603 1975,595 r0 top (schematic designator R55)
R31 "CRCW06030000Z0EA" 0603 1950,350 r270 top (schematic designator R52)
R32 "CRCW06030000Z0EA" 0603 2055,350 r270 top (schematic designator R53)
R33 "" 0603 2230,880 r180 top (schematic designator R14)
R34 "CRCW06030000Z0EA" 0603 2145,350 r270 top (schematic designator R54)
R35 "" 0603 2325,1510 r180 top (schematic designator R63)
R36 "RC0603FR-0710RL" 0603 2463.53,1683.54 r180 top (schematic designator R20)
R37 "CRCW06031K00FKEA" 0603 2385,2015 r180 top (schematic designator R17)
R38 "" 0603 2383.53,1886.93 r180 top (schematic designator R19)
R39 "CRCW06030000Z0EA" 0603 2248.53,1886.93 r0 top (schematic designator R18)
R40 "CRCW0603806RFKEA" 0603 2163.53,1716.93 r0 top (schematic designator R16)
R41 "" 0603 2745,895 r180 top (schematic designator R5)
R42 "WSLP2726L7000FEA-ND" RES_WSLP2726 2729,2215 r270 top (schematic designator R1)
R43 "" 0603 2855,1515 r180 top (schematic designator R62)
R44 "CRCW0603806RFKEA" 0603 2943.97,2016.46 r0 top (schematic designator R9)
R45 "" 0603 2943.97,1877.13 r180 top (schematic designator R11)
R46 "CRCW06030000Z0EA" 0603 2773.97,1872.13 r0 top (schematic designator R10)
R47 "RC0603FR-0710KL" 0603 2698.97,1712.13 r0 top (schematic designator R6)
R48 "RC0603FR-0711RL" 0603 3023.97,1707.13 r180 top (schematic designator R12)
R49 "" 0603 3835,1730 r180 top (schematic designator R28)
R50 "CRCW060310K2FKEA" 0603 4355,2025 r270 top (schematic designator R27)
R51 "CRCW060311K3FKEA" 0603 4460,1990 r0 top (schematic designator R25)
R52 "RC0603FR-071K2L" 0603 4420.02,2282.27 r0 bottom (schematic designator R23)
R53 "RC0603FR-071K2L" 0603 3808.5,2145 r180 bottom (schematic designator R30)
R54 "RC0603FR-071K2L" 0603 3550,2229.68 r0 bottom (schematic designator R29)
R55 "" 0603 3045,1445 r180 bottom (schematic designator R15)
R56 "" 0603 2860,1465 r180 bottom (schematic designator R4)
R57 "CRCW12060000Z0EA" 1206 2455,2050 r0 bottom (schematic designator R22)
R58 "" 0603 2515,1445 r180 bottom (schematic designator R37)
R59 "" 0603 2325,1445 r180 bottom (schematic designator R13)
R60 "" 0603 1210,1520 r180 bottom (schematic designator R64)
R61 "" 0603 1210,1455 r180 bottom (schematic designator R43)
R62 "CRCW12060000Z0EA" 1206 980,2385 r270 top (schematic designator R60)
R63 "RC0603FR-0710KL" 0603 2698.97,1647.13 r0 top
R64 "CRCW0603806RFKEA" 0603 2943.97,1946.46 r0 top
R65 "" 0603 3023.97,1642.13 r0 top
R66 "CRCW0603806RFKEA" 0603 2163.53,1786.93 r0 top
R67 "CRCW06031K00FKEA" 0603 2385,1950 r180 top
R68 "" 0603 2463.53,1618.54 r0 top
R69 "CRCW060332K4FKEA" 0603 4460,2055 r0 top
R70 "" 0603 1380,1805 r270 top
R71 "" 0603 1300,2015 r0 top
R72 "" 0603 915,1735 r90 top
R73 "" 0603 980,1735 r90 top
R74 "" 0603 2795,2025 r180 top
R75 "" 0603 4080,2120 r270 top
R76 "" 0603 4147,2119 r270 top
R77 "CRCW060332K4FKEA" 0603 190,2255 r0 top
R78 "" 0603 4200,2360 r270 top
R79 "" 0603 4130,2360 r270 top
R80 "" 0603 1555,1505 r180 top
R81 "" 0603 1530,1900 r0 top
R82 "" 0603 1315,1805 r90 top
R83 "" 0603 1670,1900 r180 top
T1 "750342271" 760390015 360,1040 r90 top (schematic designator T2)
T2 "750342271" 760390015 3890,1035 r90 top (schematic designator T1)
TP1 "" TP-040_RND 340,2600 r0 top
TP2 "" TP-040_RND 2875,610 r90 top (schematic designator TP6)
TP3 "" TP-040_RND 4570,2380 r0 top (schematic designator TP5)
TP4 "" TP-040_RND 3220,1425 r90 top
TP5 "" TP-040_RND 4080,2240 r90 top
TP6 "" TP-040_RND 1415,2135 r90 top
TP7 "" TP-040_RND 1685,1570 r90 top
TP8 "" TP-040_RND 1700,1985 r0 top
TP9 "" TP-040_RND 2595,1910 r0 top
TP12 "" TP-040_RND 2995,1550 r90 top
TP13 "" TP-040_RND 3355,1555 r90 top
TP14 "" TP-040_RND 1210,1810 r90 top
TP15 "" TP-040_RND 2465,1535 r90 top
TP18 "" TP-040_RND 915,1565 r90 top
TP19 "" TP-040_RND 720,2370 r90 top
U1 "TPS7A3001DGNR" DGN0008D_N 165,2000 r270 top (schematic designator U16)
U2 "SN6501DBV" DBV0005A_N 460,885 r270 top (schematic designator U13)
U3 "TLV70450DBV" DBV0005A_N 508.47,2004.8 r180 top (schematic designator U9)
U4 "TPS70925DBVR" DBV0005A_N 745,1805 r90 top (schematic designator U17)
U5 "AMC1304M25DW" DW0016B_N 1231.5,1176.5 r270 top (schematic designator U11)
U6 "OPA188AIDBVR" DBV0005A_N 1510,1795 r180 top
U7 "CDCLVC1104PW" PW0008A_N 1730,666.46 r180 top (schematic designator U15)
U8 "AMC1304M05DWR" DW0016B_N 2332,1165 r270 top (schematic designator U3)
U9 "AMC1304M05DWR" DW0016B_N 2855.32,1165 r270 top (schematic designator U2)
U10 "OPA188AIDBVR" DBV0005A_N 2860,1775 r180 top
U11 "TLV70450DBV" DBV0005A_N 3565.31,1805.98 r180 top (schematic designator U9)
U12 "TPS70925DBVR" DBV0005A_N 3840,1850 r90 top
U13 "SN6501DBV" DBV0005A_N 3990,880 r270 top (schematic designator U6)
U14 "TPS7A3001DGNR" DGN0008D_N 4425.31,1825 r270 top (schematic designator U8)
U15 "OPA188AIDBVR" DBV0005A_N 2323.53,1786.93 r180 top
ZZ1 "This Assembly Note is for PCB labels only" AssemblyNoteLabel 140,5808 r0 top
ZZ2 "These assemblies are ESD sensitive, ESD precautions shall be observed." AssemblyNote 140,5699.11 r0 top
ZZ3 "These assemblies must be clean and free from flux and all contaminants. Use of no clean flux is not acceptable." AssemblyNote 140,5610.56 r0 top
ZZ4 "These assemblies must comply with workmanship standards IPC-A-610 Class 2, unless otherwise specified." AssemblyNote 140,5522 r0 top

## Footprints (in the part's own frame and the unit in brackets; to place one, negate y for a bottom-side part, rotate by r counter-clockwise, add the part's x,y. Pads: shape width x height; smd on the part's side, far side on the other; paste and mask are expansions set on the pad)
0603 [mm] "0603 from SM-752 data"
  rect 1x0.95 smd: 1(-0.8,0) 2(0.8,0)
  silkscreen extent -1.52,-0.69 1.52,0.69, body extent -0.87,-0.47 0.87,0.47, height 1
0805_HV [mil] "0805 with 30mil clearance between pads"
  rect 50x63 smd: 1(-40,0) 2(40,0)
  silkscreen extent -74,-40 74,40, body extent -43,-29 43,29, height 57
1206 [mm] "1206 from SM-752 data"
  rect 1.3x1.85 smd: 1(-1.45,0) 2(1.45,0)
  silkscreen extent -2.4,-1.21 2.4,1.21, body extent -1.7,-0.9 1.7,0.9, height 1.35
1210 [mm] "1210 from SM-752 data"
  rect 1.3x2.7 smd: 1(-1.45,0) 2(1.45,0)
  silkscreen extent -2.32,-1.57 2.32,1.57, body extent -1.7,-1.35 1.7,1.35, height 1.35
760390015 [mm]
  rect 1.27x0.66 smd: 1(0,0) 2(0,-2.54) 3(0,-5.08) 4(9.14,-5.08) 5(9.14,-2.54) 6(9.14,0)
  silkscreen extent -1.75,-6.35 10.2,1.59, body extent -1,-6.4 10.2,1.2, height 4.2
AssemblyNote [mil] "Assembly Note"
AssemblyNoteLabel [mil] "Assembly Note for PCB Labels"
CAP_200mil [mil]
  round 60 hole 32 mask+5: 1(-100,0) 2(100,0)
CONN_ED120-2DS [mm] "ONSHORE"
  rect 1.75x1.75 hole 1.25: 1(0,-2.54)
  round 1.75 hole 1.25: 2(0,2.54)
  silkscreen extent -5,-5.6 4,5.12, body extent -5,-5.6 4.15,5.12, height 13.1
CONN_NRPN302PAEN-RC [mil]
  rect 56x56 hole 31: 1(-1141.73,-39.37)
  round 56 hole 31: 2(-1141.73,39.37) 3(-1062.99,-39.37) 4(-1062.99,39.37) 5(-984.25,-39.37) 6(-984.25,39.37) 7(-905.51,-39.37) 8(-905.51,39.37) 9(-826.77,-39.37) 10(-826.77,39.37) 11(-748.03,-39.37) 12(-748.03,39.37) 13(-669.29,-39.37) 14(-669.29,39.37) 15(-590.55,-39.37) 16(-590.55,39.37) 17(-511.81,-39.37) 18(-511.81,39.37) 19(-433.07,-39.37) 20(-433.07,39.37) 21(-354.33,-39.37) 22(-354.33,39.37) 23(-275.59,-39.37) 24(-275.59,39.37) 25(-196.85,-39.37) 26(-196.85,39.37) 27(-118.11,-39.37) 28(-118.11,39.37) 29(-39.37,-39.37) 30(-39.37,39.37) 31(39.37,-39.37) 32(39.37,39.37) 33(118.11,-39.37) 34(118.11,39.37) 35(196.85,-39.37) 36(196.85,39.37) 37(275.59,-39.37) 38(275.59,39.37) 39(354.33,-39.37) 40(354.33,39.37) 41(433.07,-39.37) 42(433.07,39.37) 43(511.81,-39.37) 44(511.81,39.37) 45(590.55,-39.37) 46(590.55,39.37) 47(669.29,-39.37) 48(669.29,39.37) 49(748.03,-39.37) 50(748.03,39.37) 51(826.77,-39.37) 52(826.77,39.37) 53(905.51,-39.37) 54(905.51,39.37) 55(984.25,-39.37) 56(984.25,39.37) 57(1062.99,-39.37) 58(1062.99,39.37) 59(1141.73,-39.37) 60(1141.73,39.37)
  body extent -1181,-79 1181,79, height 220
DBV0005A_N [mm] "SOT23, 5-Leads, Body 2.9x1.6mm, Pitch 0.95mm, Lead Span 2.8mm, IPC Medium Density"
  rrect17% 1x0.6 smd: 1(-1.375,0.95) 2(-1.375,0) 3(-1.375,-0.95) 4(1.375,-0.95) 5(1.375,0.95)
  silkscreen extent -1.63,-1.55 0.38,1.55, body extent -1.42,-1.46 1.42,1.46, height 1.09
DGN0008D_N [mm] "TSOP, 8-Leads, Body 3x3mm, Pitch 0.65mm, Thermal Pad 1.89x1.57mm, IPC Medium Density"
  rrect100% 1.35x0.45 smd: 1(-2.225,0.975) 2(-2.225,0.325) 3(-2.225,-0.325) 4(-2.225,-0.975) 5(2.225,-0.975) 6(2.225,-0.325) 7(2.225,0.325) 8(2.225,0.975)
  rrect6% 1.57x1.89 smd: 9(0,0)
  silkscreen extent -2.73,-1.55 0.95,1.55, body extent -2.46,-1.5 2.46,1.5, height 1.1
DW0016B_N [mm] "SOIC, 16-Leads, Body 10.5x7.6mm, Pitch 1.27mm, IPC Medium Density"
  rrect17% 1.9x0.6 smd: 1(-4.75,4.445) 2(-4.75,3.175) 3(-4.75,1.905) 4(-4.75,0.635) 5(-4.75,-0.635) 6(-4.75,-1.905) 7(-4.75,-3.175) 8(-4.75,-4.445) 9(4.75,-4.445) 10(4.75,-3.175) 11(4.75,-1.905) 12(4.75,-0.635) 13(4.75,0.635) 14(4.75,1.905) 15(4.75,3.175) 16(4.75,4.445)
  silkscreen extent -5.6,-5.25 3.4,5.25, body extent -5.17,-5.15 5.17,5.15, height 2.59
Fiducial10-20 [mm]
  round 1 smd mask+0.5: 1(0,0)
  Top Layer keep-out circle w1.178: c0,0 r0.5
Keystone_1902C [mil] "Hex Standoff, 4-40 threaded, nylon"
  body extent -145,-126 146,126, height 501
Label_650x200 [mil] "Thermal Transfer Label"
  silkscreen extent -325,-100 325,100, body extent -326,-101 326,101, height 1
LED0603AA [mil]
  rect 32x32 smd: 1(-32.48,0) 2(32.48,0)
  silkscreen extent -132,-25 7,25
MMZ1608_095 [mm] "TDK"
  rect 0.6x0.8 smd: 1(-0.7,0) 2(0.7,0)
  silkscreen extent -0.15,-0.58 0.15,0.58, body extent -0.87,-0.47 0.87,0.47, height 0.95
Molex_22-11-2032 [mm] "Header, 2.54mm, 3x1, TH"
  rect 1.6x1.6 hole 1.07: 1(-2.54,0)
  round 1.6 hole 1.07: 2(0,0) 3(2.54,0)
  silkscreen extent -3.73,-3.1 3.73,3.25, body extent -3.73,-3.1 3.73,3.25, height 10.67
"NY PMS 440 0025 PH" [mm] "4-40 nylon screw and mounting hole"
  round 8 hole 3.2: 1(0,0)
  body extent -3.3,-3.3 3.3,3.3, height 2.69
PANDUIT_LAMA2-14-QY [mil] "MECHANICAL LUG ALUM 2-14 AWG,TH"
  rect 1161.42x500 hole 270 copper offset -269.69,0: 1(0,0)
  silkscreen extent -870,-270 331,270, body extent -850,-250 311,250, height 551
powerDI123 [mm] "Diodes Inc recommended land pattern, document number DS30628 Rev. 6-2"
  rect 2.2x1.4 smd: 1(-1.275,0)
  rect 0.9x1.4 smd: 2(1.275,0)
  silkscreen extent -3.1,-1.09 1.76,1.09, body extent -2.37,-0.96 1.53,0.97, height 1
PW0008A_N [mm] "TSOP, 8-Leads, Body 3x4.4mm, Pitch 0.65mm, IPC Medium Density"
  oval 1.4x0.45 smd: 1(-2.95,0.975) 2(-2.95,0.325) 3(-2.95,-0.325) 4(-2.95,-0.975) 5(2.95,-0.975) 6(2.95,-0.325) 7(2.95,0.325) 8(2.95,0.975)
  silkscreen extent -3.4,-1.55 1.85,1.55, body extent -3.21,-1.5 3.21,1.5, height 1.2
RES_WSLP2726 [mil]
  rect 220x96 smd: 1(-35,97) 2(-35,-97)
  rect 35x96 smd: 1A(127.5,97) 2A(127.5,-97)
  silkscreen extent -130,-40 130,40, body extent -130,-136 130,136, height 149
SM_RADIAL_5MM [mm] "Nichicon 5x5.8"
  rect 3x1.6 smd: 1(-2.2,0) 2(2.2,0)
  silkscreen extent -2.75,-2.75 2.75,2.75, body extent -2.75,-2.75 2.75,2.75, height 6.1
SOD-123 [mm] "On Semi recommended land pattern"
  rect 0.915x1.22 smd: 1(-1.637,0) 2(1.637,0)
  silkscreen extent -2.74,-1.17 2.03,1.17, body extent -1.93,-0.9 1.93,0.9, height 1.35
SOT-323 [mm] "Zetex recommended land pattern.  March 2007"
  rect 0.8x0.6 smd: 1(-0.8,0.65) 2(-0.8,-0.65) 3(0.8,0)
  silkscreen extent -1.14,-1.22 0.77,1.22, body extent -1.13,-1.13 1.12,1.12, height 1.13
TI_Stacked_Overlay_Small [mil]
  silkscreen extent -418,-98 418,98
TP-040_RND [mil]
  round 70 / inner round 62 / far side round 62 hole 40: 1(0,0)

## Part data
C1 C3 C61 C62: library part 06031C103JAT2A, "CAP, CERM, 0.01uF, 100V, +/-5%, X7R, 0603"
C2 C5 C6 C9 C10 C11 C13 C17 C18 C19 C20 C21 C23 C29 C30 C31 C33 C36 C38 C39 C41 C42 C51 C53 C54 C55 C56 C57 C60 C63 C71 C83 C84: library part C0603C104K5RACTU, "CAP, CERM, 0.1uF, 50V, +/-10%, X7R, 0603"
C4 C7 C12 C49 C64 C65 C67 C68 C69 C70 C72 C73 C76 C78 C79 C80 C81: library part GMK325AB7106MM-T, "CAP, CERM, 10uF, 35V, +/-20%, X7R, 1210"
C8 C16 C50 C52 C66 C82: library part C2012X5R1H475K125AB, "CAP, CERM, 4.7uF, 50V, +/-10%, X5R, 0805"
C14 C58: "CAP, AL, 22uF, 25V, +/-20%, 0.76 ohm, SMD"
C15 C59: library part 202R18W102KV4E, "CAP CER 1000PF 1KV 10% RADIAL"
C22: "CAP, CERM, 0.01 µF, 50 V, +/- 5%, C0G/NP0, 0805"
C24 C35 C44: "CAP, CERM, 2.2 µF, 10 V, +/- 10%, X7R, 0603"
C25 C34 C43: library part 06033C104JAT2A, "CAP, CERM, 0.1uF, 25V, +/-5%, X7R, 0603"
C26 C27 C74: "CAP, CERM, 0.1uF, 25V, +/-5%, X7R, 0603"
C28 C32 C46: "CAP, CERM, 0.1 µF, 100 V, +/- 10%, X7R, 0603"
C37 C40 C45: "CAP, CERM, 1000 pF, 50 V, +/- 1%, C0G/NP0, 0603"
C75: "CAP, CERM, 1uF, 10V, +/-10%, X7R, 0603"
D1 D5 D7 D13 D14 D18: library part "LED_LG L29K-G2J1-24-Z", "LED SmartLED Green 570NM"
D2 D8 D15 D19: "Diode, Zener, 3.9 V, 500 mW, SOD-123"
D3 D6 D16 D17: library part MBR0520LT1G, "Diode, Schottky, 20V, 0.5A, SOD-123"
D4 D12: library part DFLZ6V2-7, "Diode, Zener, 6.2V, 1W, PowerDI123"
D9 D10 D11: "Diode, Schottky, 30 V, 0.2 A, SOT-323"
FID1 FID2 FID3 FID4 FID5 FID6: "Fiducial mark.  There is nothing to buy or mount."
H1 H2 H3 H4: "Machine Screw, Round, #4-40 x 1/4, Nylon, Philips panhead"
H5 H6 H7 H8: "Standoff, Hex, 0.5\"L #4-40 Nylon"
J1: "TERMINAL BLOCK 5.08MM VERT 2POS, TH"
J2: library part CON-NRPN302PAEN-RC, "CONN HEADER 2MM DUAL STR 60POS"
J3: "Header, 2.54 mm, 3x1, TH"
J4 J5: "MECHANICAL LUG ALUM 2-14 AWG"
L1 L2 L5 L8 L9 L11 L14 L15 L16 L17: "Ferrite Bead, 1000 ohm @ 100 MHz, 0.3 A, 0603"
L6: "Ferrite Bead, 600 ohm @ 100MHz, 1.3A, 0603"
LBL1: library part THT-14-423-10, "Thermal Transfer Printable Labels, 0.650\" W x 0.200\" H - 10,000 per roll"
Logo1: library part TI_Logo, "Texas Instrument Corporate Signature"
R1 R50: "RES, 10.2 k, 1%, 0.1 W, 0603"
R2 R4 R5 R52 R53 R54: "RES, 1.20 k, 1%, 0.1 W, 0603"
R3 R51: "RES, 11.3 k, 1%, 0.1 W, 0603"
R6 R49: library part CRCW06033K90JNEA, "RES, 3.9k ohm, 5%, 0.1W, 0603"
R7 R57 R62: "RES, 0, 5%, 0.25 W, 1206"
R8: library part RC1206FR-072K4L, "RES SMD 1.02K OHM 1% 1/4W 1206"
R9: "RES, 2.40 k, 1%, 0.25 W, 1206"
R10 R33 R41: library part CRCW060310R0FKEA, "RES, 10.0 ohm, 1%, 0.1W, 0603"
R11 R35 R38 R43 R45 R55 R56 R58 R59 R60 R61 R65 R68 R70 R71 R72 R73 R74 R75 R76 R78 R79 R80 R81 R82 R83: library part CRCW06030000Z0EA, "RES, 0 ohm, 5%, 0.1W, 0603"
R12 R18 R21 R23 R24 R27 R28 R31 R32 R34: "RES, 0 ohm, 5%, 0.1W, 0603"
R13 R14 R15 R16 R17: "RES, 332 k, 1%, 0.25 W, 1206"
R19 R36: "RES, 10.0, 1%, 0.1 W, 0603"
R20: "RES, 100 k, 5%, 0.1 W, 0603"
R22 R25 R26 R29: "RES, 100, 1%, 0.1 W, 0603"
R30: "RES, 1.0k ohm, 5%, 0.1W, 0603"
R37 R67: "RES, 1.00 k, 1%, 0.1 W, 0603"
R39 R46: "RES, 0, 5%, 0.1 W, 0603"
R40 R44 R64 R66: "RES, 806, 1%, 0.1 W, 0603"
R42: library part WSLP2726L5000FEA, "RES SMD 0.0007 OHM 1% 7W 2726"
R47 R63: "RES, 10.0 k, 1%, 0.1 W, 0603"
R48: "RES, 11.0, 1%, 0.1 W, 0603"
R69 R77: "RES, 32.4 k, 1%, 0.1 W, 0603"
T1 T2: library part TRNSFMR, "Transformer 469uH SMD"
TP1 TP2 TP3 TP4 TP5 TP6 TP7 TP8 TP9 TP12 TP13 TP14 TP15 TP18 TP19: library part TP-040_RND, "Test Point, O.040 Hole"
U1 U14: "-36V, -200mA, Ultralow-Noise, Negative Linear Regulator"
U2 U13: "Transformer Driver for Isolated Power Supplies, DBV0005A"
U3 U11: "Regulator, LDO, 5V, 0.15A, SOT23-5"
U4 U12: "150-mA, 30-V, 1-µA IQ Voltage Regulator with Enable, DBV0005A"
U5: "20 MHz, Isolated Delta-Sigma Modulator, DW0016B"
U6 U10 U15: "Precision, Low-Noise, Rail-to-Rail Output, 36 V, Zero-Drift Operational Amplifiers, DBV0005A"
U7: "3.3 V and 2.5 V LVCMOS High-Performance Clock Buffer"
U8 U9: library part AMC1304M25DW, "High-Precision, Reinforced Isolated Delta-Sigma Modulators with LDO, DW0016B"
ZZ1: library part AssemblyNoteLabel
ZZ2 ZZ3 ZZ4: library part AssemblyNote

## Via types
v1: diameter 32, hole 16, Top Layer to Bottom Layer, tented both sides, 183 vias
v2: diameter 40, hole 20, Top Layer to Bottom Layer, tented both sides, 28 vias
v3: diameter 19.68, hole 7.87, Top Layer to Bottom Layer, tented both sides, 10 vias

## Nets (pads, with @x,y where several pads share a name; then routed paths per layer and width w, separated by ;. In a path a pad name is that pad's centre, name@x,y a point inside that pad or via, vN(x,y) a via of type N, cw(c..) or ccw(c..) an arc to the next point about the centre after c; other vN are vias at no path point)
+2.5V_PH: C16.2 C17.1 D8.1 R5.2 R72.1 TP18.1 U4.5 | length 1114.6
  Top Layer w20: v1(655,2025) 702.5,2025 707.5,2020 C17.1@708.5,2021 ; U4.5@707.6,1859.13 707.6,1936.4 C16.2@705,1939 708.5,1942.5 C17.1@708.5,2021 ; R5.2@708.5,2190 703,2184.5 703,2153 685.53,2135.53 D8.1@685.53,2105 708.5,2082.03 C17.1@708.5,2021 ; TP18.1@915,1565 R72.1@915,1703.5
  Bottom Layer w20: v1(655,2025) 655,1975 915,1715 TP18.1@915,1565
+2.5V_USH: C52.2 C55.1 D15.1 R53.2 R75.1 TP5.1 U12.5 | length 957.1
  Top Layer w20: U12.5@3802.6,1904.13 3802.6,1977.6 C52.2@3805,1980 ; v1(4025,2150) 4078.5,2150 R75.1@4080,2151.5 TP5.1@4080,2240
  Top Layer w25: v1(3720,2080) 3720,2120 3745,2145 3780.53,2145 3808.5,2117.03 C55.1@3808.5,2060 3808.5,1983.5 C52.2@3805,1980
  Bottom Layer w20: v1(3720,2080) 3955,2080 v1(4025,2150)
  Bottom Layer w25: v1(3720,2080) 3720,2130 3735,2145 R53.2@3777.01,2145
+3.3V_DVDD: C75.1 J2.1 J3.2 L5.2 L6.1 L9.2 L14.2 R30.2 TP2.1 | length 260.7
  Top Layer w20: L5.2@1287.44,770 1287.44,727.56 v1(1290,725) ; v1(1365,721.46) 1408.5,721.46 L6.1@1410,722.95 ; v1(2006.5,546.5) R30.2@2006.5,595 ; L9.2@2477.56,760 v1(2515,760) ; L14.2@3007.56,765 v1(3045,765)
  Bottom Layer w20: v1(1365,721.46) 1366.5,722.95 C75.1@1410,722.95
+5.0V_PH: C8.2 C9.1 D4.1 L2.2 L17.2 R4.2 R73.1 TP19.1 | length 493.6
  Top Layer w20: R4.2@516.5,2530 510.2,2523.7 D4.1@510.2,2450 529.5,2430.7 C9.1@529.5,2364 ; v1(584,2364) C9.1@529.5,2364 ; L2.2@625,2280.56 535.56,2280.56 C8.2@535,2280 535,2358.5 C9.1@529.5,2364 ; v1(980,1655) R73.1@980,1703.5
  Bottom Layer w20: v1(1085,1735) L17.2@1122.44,1735
+5.0V_USH: C50.2 C71.1 D12.1 L8.2 L11.2 L15.2 R54.2 R76.1 TP4.1 | length 603.3
  Top Layer w20: v1(2095,1570) L8.2@2137.44,1570 ; v1(2645,1555) 2660,1570 L11.2@2742.44,1570 ; R76.1@4147,2150.5 4199.5,2150.5 v1(4200,2150)
  Top Layer w25: D12.1@3585.2,2159.68 3600,2144.88 C50.2@3600,2059.68 3662.56,2059.68 L15.2@3685,2037.24 ; 3631.5,2159.68 3674.69,2159.68 v1(3675,2160)
  Bottom Layer w25: v1(3555,2285) 3581.5,2258.5 R54.2@3581.5,2229.68 ; C71.1@3581.5,2159.68 3674.69,2159.68 v1(3675,2160)
+5V_CNTL: C13.2 C14.1 C57.2 C58.1 J2.2 J3.3 T1.2 T2.2 U2.2 U13.2 | length 5419.7
  Top Layer w25: T1.2@460,1040 U2.2@460,939.13 460,900 475,885 505,885 516.5,896.5 C13.2@570,896.5 613.5,896.5 665,845 C14.1@693.39,845 693.39,621.35 1095.37,219.37 ; J2.2@1223.27,219.37 1095.37,219.37 ; T2.2@3990,1035 U13.2@3990,934.13 3990,900 4000,890 C57.2@4095,890 ; C57.2@4095,891.5 4128.5,891.5 4180,840 C58.1@4203.39,840 4203.39,678.39 3600,75 1099,75 J3.3@1025,149 1095.37,219.37
+6V_PH: C10.1 C11.1 C12.1 C18.1 C78.2 C79.2 D6.1 R6.2 U3.2 U4.1 | length 705.9
  Top Layer w25: v1(490,1770) 491.98,1771.98 C11.1@491.98,1824.8 C10.1@491.98,1894.8 508.47,1911.3 508.47,1985.12 528.16,2004.8 U3.2@562.61,2004.8 ; v1(601,1749) 622.09,1727.91 C12.1@622.09,1640
  Bottom Layer w25: v1(417.09,1835) 457.09,1835 467.09,1825 475,1832.91 475,1895 v1(417.09,1895) ; v1(601,1749) 622.09,1727.91 C78.2@622.09,1640
+6V_USH: C51.1 C53.1 C54.1 C68.1 C69.2 C70.2 D16.1 R49.2 U11.2 U12.1 | length 628.7
  Top Layer w25: C51.1@3596.81,1685.98 3596.81,1723.19 3565,1755 3565,1785 3585.98,1805.98 U11.2@3619.45,1805.98
  Bottom Layer w20: v1(3680,1670) 3646.77,1670 C70.2@3627.09,1689.68 3627.09,1720 v1(3680,1720) ; v1(3725,1670) 3757.91,1670 C69.2@3777.91,1690 3777.91,1720 v1(3725,1720) ; v1(3745,1470) 3782.91,1470 C68.1@3807.91,1495 3807.91,1522.91 3805.83,1525 v1(3745,1525)
-2.5V_PH: C2.1 C23.2 C82.2 D2.2 D9.1 L1.2 R2.2 TP1.1 U6.2 | length 2411.6
  Top Layer w20: C2.1@221.5,2382.5 221.5,2424.53 D2.2@264.47,2467.5 215.5,2516.47 R2.2@215.5,2550.5 290.5,2550.5 TP1.1@340,2600 ; v1(284,2382.5) 284.56,2383.06 L1.2@336,2383.06 ; v1(1525,2070) 1525.59,2069.41 D9.1@1525.59,2021.5 ; U6.2@1564.13,1795 C23.2@1648.5,1795 v1(1648.5,1845)
  Top Layer w25: C2.1@221.5,2382.5 v1(284,2382.5)
  Bottom Layer w20: v1(284,2382.5) 356.33,2310.17 356.33,2276.33 417.67,2215 1445,2215 1525,2135 v1(1525,2070) 1648.5,1946.5 v1(1648.5,1845) v1@1650,1846.5
  Bottom Layer w25: C82.2@230,2387.5 235,2382.5 v1(284,2382.5)
-2.5V_USH: C60.1 C66.2 D19.2 L16.2 R52.2 R78.1 TP3.1 | length 919.4
  Top Layer w20: R78.1@4200,2391.5 4271.5,2391.5 4337.27,2457.27 4492.73,2457.27 TP3.1@4570,2380 4570,2310 4542.27,2282.27 v1(4530.02,2282.27) D19.2@4484.49,2282.27 ; C60.1@4451.51,2197.27 4453.95,2194.83 v1(4510.02,2194.83) L16.2@4555.02,2194.83
  Bottom Layer w20: v1(4510.02,2194.83) 4461.47,2194.83 4451.51,2204.79 R52.2@4451.51,2282.27 v1(4530.02,2282.27)
-6V_PH: C4.2 C5.1 C6.2 C80.2 D3.2 U1.5 U1.8 | length 489.5
  Top Layer w15: v1(87,1912) 126.21,1912 U1.5@126.61,1912.4 ; U1.8@203.39,1912.4 C5.1@273.9,1912.4
  Bottom Layer w15: v1@86,1911 v1(87,1912)
  Bottom Layer w20: v1(250,1829) 250,1887.28 255.63,1892.91 C80.2@280,1892.91 301.09,1892.91 315,1879 v1(315,1830)
  Bottom Layer w25: v1(87,1912) 115.27,1912 198.27,1829 v1(250,1829)
-6V_USH: C56.2 C63.1 C64.2 C67.2 D17.2 U14.5 U14.8 | length 401.6
  Top Layer w15: 4335,1737.4 U14.5@4386.93,1737.4
  Top Layer w25: v1(4232.09,1527.91) v1@4235,1525
  Bottom Layer w25: v1(4230,1470) 4169.17,1470 4167.09,1472.09 C67.2@4167.09,1495 4167.09,1527.91 v1(4232.09,1527.91) ; v1(4523.07,1708.07) 4523.07,1756.93 4526.14,1760 4580,1760 v1(4580,1706.14)
CLK_IN: J2.5 R18.2 R21.1 | length 334
  Top Layer w8: J2.5@1380.75,140.63 1341.75,179.63 1341.75,235.52 1355,248.78 R18.2@1355,318.5 1383.5,318.5 1395,330 1395,370 1406.5,381.5 R21.1@1440,381.5
CLK_OUT: R12.1 R18.1 R26.2 | length 601.5
  Top Layer w10: R12.1@1275,381.5 R18.1@1355,381.5 1355,460 1390,495 1720,495 1728.5,503.5 R26.2@1728.5,555
CLKP_CH_U: R29.1 U9.13 | length 1095.2
  Top Layer w10: R29.1@2006.5,660 2715.32,660 2880.32,825 U9.13@2880.32,977.99
CLKP_CH_V: R25.1 U8.13 | length 828.8
  Top Layer w10: R25.1@1721.5,780 1722.95,781.46 2326.46,781.46 2357,812 U8.13@2357,977.99 U8.13@2357,992
CLKP_U_PH: R22.1 U5.13 | length 571.7
  Top Layer w10: U5.13@1256.5,989.49 1256.5,648.5 1350,555 R22.1@1448.5,555
DGND: C13.1 C14.2 C15.1 C24.1 C25.1 C26.2 C27.2 C34.1 C35.1 C43.1 C44.1 C57.1 C58.2 C59.1 C74.2 C75.2 J2.22 J2.39 J2.40 J2.59 J2.60 J3.1 U2.4 U2.5 U5.9 U5.16 U7.4 U8.9 U8.16 U9.9 U9.16 U13.4 U13.5 | length 1450.5
  Top Layer w15: U7.4@1846.14,704.84 1883.84,704.84 v1(1904,725)
  Top Layer w20: v1(422.6,782.6) U2.4@422.6,830.87 ; C24.1@1396.5,835 v1(1450,835) ; C25.1@1397.99,901.5 1448.5,901.5 v1(1450,900) ; U5.16@1406.5,989.49 1409.49,986.5 v1(1466.5,986.5) ; C26.2@1475,727.95 C27.2@1540,727.95 ; C27.2@1540,722.95 C27.2@1540,727.95 ; v1(1540,775) C27.2@1540,727.95 ; C35.1@2486.5,830 v1(2535,830) ; C34.1@2486.5,895 v1(2535,895) ; U8.16@2507,965.68 v1(2554.32,965.68) ; C44.1@3016.5,830 v1(3065,830) ; C43.1@3016.5,895 v1(3070,895) ; v1(3952.6,777.6) U13.4@3952.6,825.87 ; v1(4095,777.6) C57.1@4095,825.87
  Top Layer w25: U2.5@497.4,830.87 567.36,830.87 C13.1@570,833.5 v1(570,785) ; C14.2@866.61,845 v1(960,845) ; v1@1009.49,989.49 U5.9@1056.5,989.49 ; v1(2103.65,966.13) 2104.1,965.68 U8.9@2157,965.68 ; v1@2633.31,977.99 U9.9@2680.32,977.99 ; U9.16@3030.32,977.99 v1@3077.32,977.99 ; U13.5@4027.4,825.87 C57.1@4095,825.87 ; C58.2@4376.61,840 4500,840 v1(4505,845)
  Bottom Layer w15: v1(1410,611.46) C75.2@1410,659.96
  Bottom Layer w20: C74.2@1475,722.95 v1(1475,775)
  other v1: 2633.31,977.01 3077.32,978.98 1009.49,988.5
DOUTP_CH_U: R31.1 R41.2 | length 1082.4
  Top Layer w10: R31.1@1950,381.5 1973.69,381.5 v1(2005,350.19) ; v1(2713.5,841.5) R41.2@2713.5,895
  Bottom Layer w10: v1(2005,350.19) 2305.13,350.19 2305.32,350 2713.5,758.19 v1(2713.5,841.5)
DOUTP_CH_V: R28.1 R33.2 | length 777.8
  Top Layer w10: R28.1@1820,381.5 1820,445 1862.08,487.08 v1(1915,487.08) ; R33.2@2198.5,880 2198.5,831.5 v1(2205,825)
  Bottom Layer w10: v1(1915,487.08) 1922.08,487.08 1975,540 1975,735 2065,825 v1(2205,825)
DOUTP_U_PH: R10.2 R23.1 | length 931.9
  Top Layer w10: R10.2@1095,911.5 1097,909.5 v1(1097,848) ; R23.1@1535,381.5 v1(1535,435)
  Bottom Layer w10: v1(1097,848) 1097,498 1160,435 v1(1535,435)
GND_PH: C1.1 C2.2 C4.1 C5.2 C6.1 C7.1 C8.1 C9.2 C10.2 C11.2 C12.2 C15.2 C16.1 C17.2 C18.2 C19.2 C20.2 C21.2 C22.1 C23.1 C28.2 C29.1 C76.1 C78.1 C79.1 C80.1 C81.1 C82.1 D1.2 D2.1 D4.2 D5.1 D7.1 D8.2 R1.1 R8.1 R9.1 R11.1 R20.1 R62.2 R83.1 T1.4 TP8.1 U1.3 U1.4 U1.9 U3.1 U4.2 U5.4 U5.8 | length 3908.2
  Top Layer w10: 140.17,2087.6 U1.3@152.2,2087.6
  Top Layer w20: v1(55,2275) 55,2268 71.5,2251.5 R1.1@95,2251.5 ; v1(80,2075) 92.6,2087.6 U1.4@126.61,2087.6 140.17,2087.6 ; v3(165,2000) 188.5,1976.5 C5.2@275,1976.5 ; U4.2@745,1750.87 v1(745,1800) ; C17.2@771.5,2021 825.5,2021 v1(826.5,2022) ; C16.1@785,1939 854,1939 v1(855,1940) ; D8.2@814.47,2105 868.47,2105 v1(869.47,2106) ; v1(970,1455) C20.2@1023.5,1455 ; v1(970,1520) C19.2@1023.5,1520 C20.2@1023.5,1455 ; U5.8@1056.5,1346.5 U5.8@1056.5,1363.5 1056.5,1393.5 1023.5,1426.5 C20.2@1023.5,1455 ; U5.4@1256.81,1363.19 U5.4@1256.5,1363.5 1256.5,1408.5 1241.5,1423.5 C21.2@1241.5,1455 1285,1455 v1(1290,1460) ; v1(1290,1645) 1331.5,1603.5 R11.1@1331.5,1571.5 ; 1701.5,1848.5 1711.5,1838.5 C23.1@1711.5,1795 1711.5,1746.5 v1(1710,1745)
  Top Layer w25: v1(76,2467.5) D2.1@135.53,2467.5 ; C1.1@88.5,1830 88.5,1783.5 v1(91,1781) ; v1(92,2382.5) C2.2@158.5,2382.5 ; D1.2@220.48,2612.5 260,2612.5 v1(261,2613.5) ; C6.1@341.5,1745 v1(400,1745) ; v1(358,2450) D4.2@409.8,2450 ; v1(370,2160) C7.1@442.91,2160 ; C4.1@387.09,1640 376.04,1651.04 390,1665 v1(445,1665) ; v1(390,2310) 420,2280 C8.1@455,2280 ; v1(412,2363) 413,2364 C9.2@466.5,2364 ; v1(445,1615) 507.91,1615 C12.2@507.91,1640 ; D5.1@517.48,2590 517.48,2638.48 v1(518,2639) ; C11.2@554.97,1824.8 C10.2@554.97,1894.8 554.97,1959.76 U3.1@562.61,1967.4 v1(612.4,1967.4) ; v1(635,1415) 570,1415 560,1405 T1.4@560,1399.84 560,1390 590,1360 695,1360 C15.2@740,1315 ; D7.1@706.52,2258 v1(706.52,2302.48) ; C18.2@784.5,1613 838,1613 v1(840,1615) ; v1(975,2262.6) 980,2267.6 R62.2@980,2327.91 ; v1(995,2015) R9.1@1067.91,2015 ; v1(995,2120) R8.1@1067.91,2120 ; v1(1190,1920) C22.1@1255,1920 ; C28.2@1383.5,1650 1383.5,1596.5 v1(1385,1595) ; v1(1465,1570) R20.1@1523.5,1570 ; TP8.1@1700,1985 1701.5,1983.5 R83.1@1701.5,1900 1701.5,1848.5
  Bottom Layer w20: v1(90,2131) 90.06,2131 104,2144.94 104,2201.09 C81.1@112.91,2210 ; v1(255,2076) 255,2007.09 C80.1@280,2007.09 305,2007.09 305,2076 v1(304,2077) ; v1(1065,1590) 1115,1590 C76.1@1121.5,1596.5 ; v1(1065,1650) 1117.09,1650 1118.58,1651.5 1119.41,1650.67 C76.1@1119.41,1621.5 ; v1(1430,1885) 1455,1860 C29.1@1455,1821.5
  Bottom Layer w25: v1(92,2382.5) 97,2387.5 C82.1@150,2387.5 ; v1(261,2613.5) v1@262,2613.5 ; v1(445,1615) 500,1615 507.91,1622.91 C78.1@507.91,1640 507.91,1662.09 505,1665 v1(445,1665) ; v1(635,1835) 582.09,1835 C79.1@582.09,1865 582.09,1895 v1(635,1895) ; v1@705,2304 v1(706.52,2302.48)
  other v3: 141.38,1982.28 188.62,1982.28 141.38,2017.72 188.62,2017.72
